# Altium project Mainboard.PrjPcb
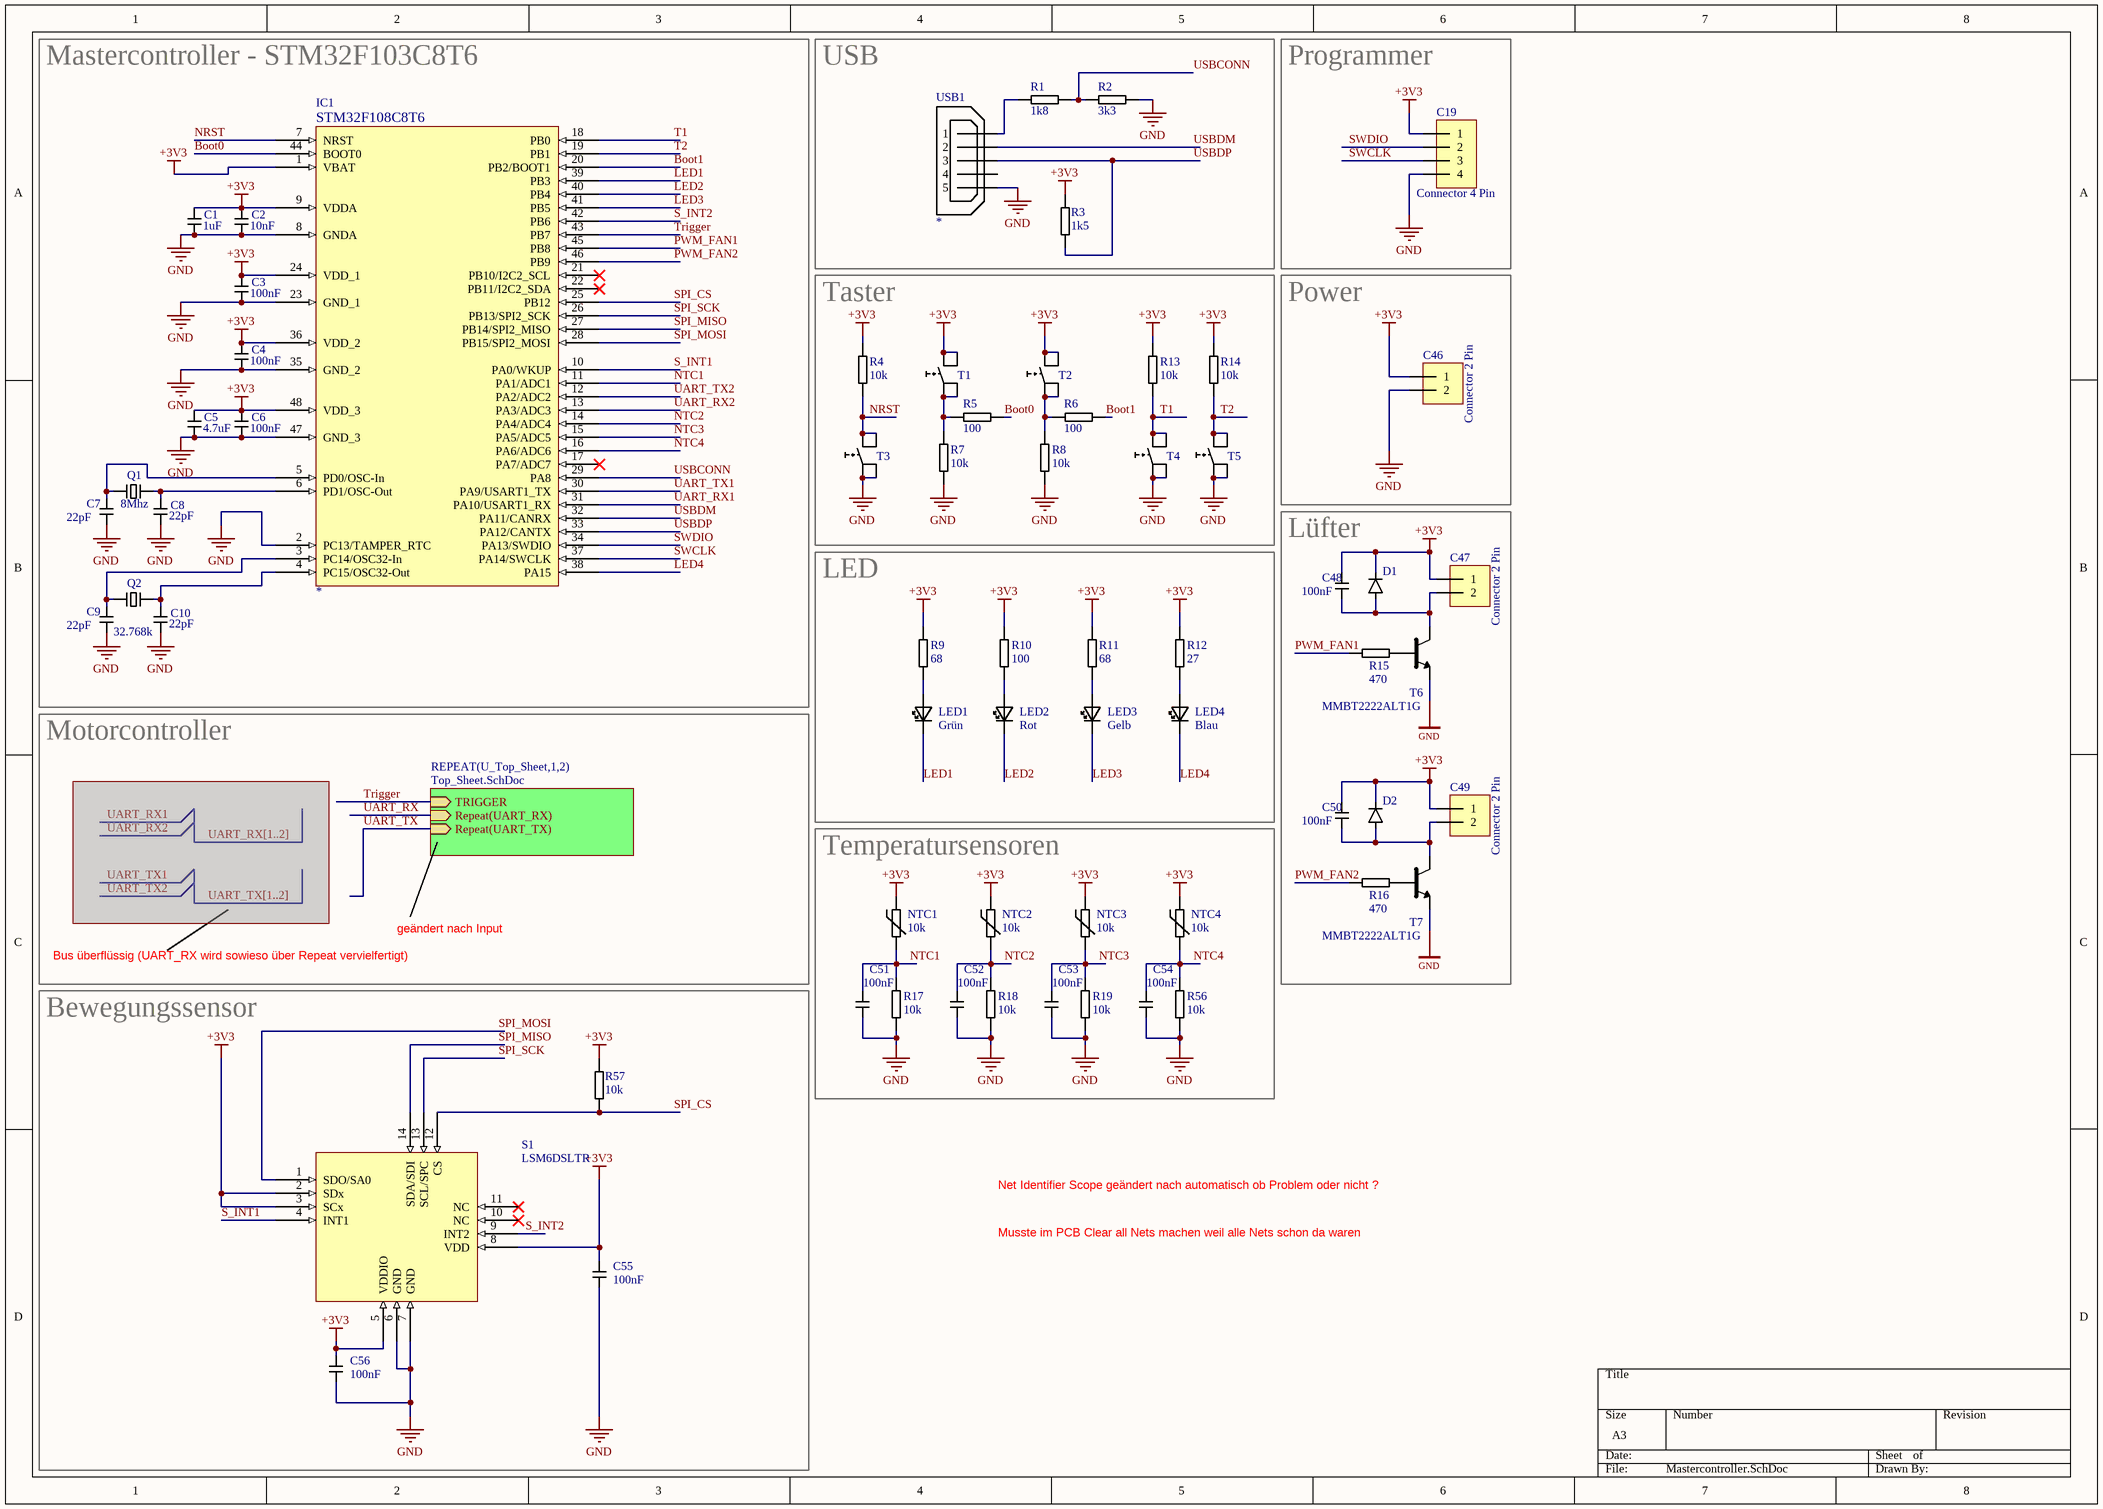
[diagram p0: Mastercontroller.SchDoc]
6 sheets, 311 parts. Net scope: hierarchical (ports join the sheet entries above them; power ports are global).
Board file: Mainboard.PcbDoc
Sheets:
  Mastercontroller.SchDoc
    U_Top_Sheet1 = Top_Sheet.SchDoc
      U_MOTOR = MOTOR.SchDoc
      U_SENSE = SENSE.SchDoc
      U_DRV8301 = DRV8301.SchDoc
      U_Motorcontroller = Motorcontroller.SchDoc
    U_Top_Sheet2 = Top_Sheet.SchDoc
      U_MOTOR = MOTOR.SchDoc
      U_SENSE = SENSE.SchDoc
      U_DRV8301 = DRV8301.SchDoc
      U_Motorcontroller = Motorcontroller.SchDoc

## Sheet Mastercontroller.SchDoc
size A3

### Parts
C1  value 1uF  [0603]  (hidden comment: *)
C2  value 10nF  [0603]  (hidden comment: *)
C3  value 100nF  [0603]  (hidden comment: *)
C4  value 100nF  [0603]  (hidden comment: *)
C5  value 4.7uF  [0603]  (hidden comment: *)
C6  value 100nF  [0603]  (hidden comment: *)
C7  value 22pF  [0603]  (hidden comment: *)
C8  value 22pF  [0603]  (hidden comment: *)
C9  value 22pF  [0603]  (hidden comment: *)
C10  value 22pF  [0603]  (hidden comment: *)
C19  Connector 4 Pin  [JST-XH 4 Pin]
C46  Connector 2 Pin  [JST-XH 2 Pin]
C47  Connector 2 Pin  [JST-XH 2 Pin]
C48  value 100nF  [0603]  (hidden comment: *)
C49  Connector 2 Pin  [JST-XH 2 Pin]
C50  value 100nF  [0603]  (hidden comment: *)
C51  value 100nF  [0603]  (hidden comment: *)
C52  value 100nF  [0603]  (hidden comment: *)
C53  value 100nF  [0603]  (hidden comment: *)
C54  value 100nF  [0603]  (hidden comment: *)
C55  value 100nF  [0603]  (hidden comment: *)
C56  value 100nF  [0603]  (hidden comment: *)
D1  Diode  [SMA]  (value not drawn)
D2  Diode  [SMA]  (value not drawn)
IC1  *  [LQFP48]
LED1  value Grün  [1206_Green]  (hidden comment: *)
LED2  value Rot  [1206_Green]  (hidden comment: *)
LED3  value Gelb  [1206_Green]  (hidden comment: *)
LED4  value Blau  [1206_Green]  (hidden comment: *)
NTC1  value 10k  [0603]  (hidden comment: NTC)
NTC2  value 10k  [0603]  (hidden comment: NTC)
NTC3  value 10k  [0603]  (hidden comment: NTC)
NTC4  value 10k  [0603]  (hidden comment: NTC)
Q1  value 8Mhz  [3225]  (hidden comment: *)
Q2  value 32.768k  [Cylinder]  (hidden comment: *)
R1  value 1k8  [0603]  (hidden comment: *)
R2  value 3k3  [0603]  (hidden comment: *)
R3  value 1k5  [0603]  (hidden comment: *)
R4  value 10k  [0603]  (hidden comment: *)
R5  value 100  [0603]  (hidden comment: *)
R6  value 100  [0603]  (hidden comment: *)
R7  value 10k  [0603]  (hidden comment: *)
R8  value 10k  [0603]  (hidden comment: *)
R9  value 68  [0603]  (hidden comment: *)
R10  value 100  [0603]  (hidden comment: *)
R11  value 68  [0603]  (hidden comment: *)
R12  value 27  [0603]  (hidden comment: *)
R13  value 10k  [0603]  (hidden comment: *)
R14  value 10k  [0603]  (hidden comment: *)
R15  value 470  [0603]  (hidden comment: *)
R16  value 470  [0603]  (hidden comment: *)
R17  value 10k  [0603]  (hidden comment: *)
R18  value 10k  [0603]  (hidden comment: *)
R19  value 10k  [0603]  (hidden comment: *)
R56  value 10k  [0603]  (hidden comment: *)
R57  value 10k  [0603]  (hidden comment: *)
S1  LSM6DSLTR  [LGA-14]
T1  Switch  [SMD_4x4]  (value not drawn)
T2  Switch  [SMD_4x4]  (value not drawn)
T3  Switch  [SMD_4x4]  (value not drawn)
T4  Switch  [SMD_4x4]  (value not drawn)
T5  Switch  [SMD_4x4]  (value not drawn)
T6  value MMBT2222ALT1G  [SOT23-BEC]  (hidden comment: *)
T7  value MMBT2222ALT1G  [SOT23-BEC]  (hidden comment: *)
USB1  *  [Micro USB]

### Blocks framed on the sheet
Mastercontroller - STM32F103C8T6: C1-C10 IC1 Q1 Q2
USB: R1-R3 USB1
Programmer: C19
Taster: R4-R8 R13 R14 T1-T5
Power: C46
LED: LED1-LED4 R9-R12
Lüfter: C47-C50 D1 D2 R15 R16 T6 T7
Temperatursensoren: C51-C54 NTC1-NTC4 R17-R19 R56
Bewegungssensor: C55 C56 R57 S1

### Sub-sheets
REPEAT(U_Top_Sheet,1,2) = Top_Sheet.SchDoc: TRIGGER (in), Repeat(UART_RX) (in), Repeat(UART_TX) (in)

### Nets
+3V3: C1.2 C2.2 C3.2 C4.2 C5.2 C6.2 C19.1 C46.1 C47.1 C48.2 C49.1 C50.2 C55.2 C56.2 D1.2 D2.2 IC1.1(VBAT) IC1.9(VDDA) IC1.24(VDD_1) IC1.36(VDD_2) IC1.48(VDD_3) NTC1.1 NTC2.1 NTC3.1 NTC4.1 R3.1 R4.2 R9.2 R10.2 R11.2 R12.2 R13.2 R14.2 R57.1 S1.2(SDx) S1.3(SCx) S1.5(VDDIO) S1.8(VDD) T1.3 T1.4 T2.3 T2.4
GND: C1.1 C2.1 C3.1 C4.1 C5.1 C6.1 C7.1 C8.1 C9.1 C10.1 C19.4 C46.2 C51.1 C52.1 C53.1 C54.1 C55.1 C56.1 IC1.2(PC13/TAMPER_RTC) IC1.8(GNDA) IC1.23(GND_1) IC1.35(GND_2) IC1.47(GND_3) R2.1 R7.1 R8.1 R17.1 R18.1 R19.1 R56.1 S1.6(GND) S1.7(GND) T3.1 T3.2 T4.1 T4.2 T5.1 T5.2 T6.E T7.E USB1.5
Boot0: IC1.44(BOOT0) R5.1
Boot1: IC1.20(PB2/BOOT1) R6.1
LED1: IC1.39(PB3) LED1.2
LED2: IC1.40(PB4) LED2.2
LED3: IC1.41(PB5) LED3.2
LED4: IC1.38(PA15) LED4.2
NRST: IC1.7(NRST) R4.1 T3.3 T3.4
NTC1: C51.2 IC1.11(PA1/ADC1) NTC1.2 R17.2
NTC2: C52.2 IC1.14(PA4/ADC4) NTC2.2 R18.2
NTC3: C53.2 IC1.15(PA5/ADC5) NTC3.2 R19.2
NTC4: C54.2 IC1.16(PA6/ADC6) NTC4.2 R56.2
PWM_FAN1: IC1.45(PB8) R15.2
PWM_FAN2: IC1.46(PB9) R16.2
S_INT1: IC1.10(PA0/WKUP) S1.4(INT1)
S_INT2: IC1.42(PB6) S1.9(INT2)
SPI_CS: IC1.25(PB12) R57.2 S1.12(CS)
SPI_MISO: IC1.27(PB14/SPI2_MISO) S1.14(SDA/SDI)
SPI_MOSI: IC1.28(PB15/SPI2_MOSI) S1.1(SDO/SA0)
SPI_SCK: IC1.26(PB13/SPI2_SCK) S1.13(SCL/SPC)
SWCLK: C19.3 IC1.37(PA14/SWCLK)
SWDIO: C19.2 IC1.34(PA13/SWDIO)
T1: IC1.18(PB0) R13.1 T4.3 T4.4
T2: IC1.19(PB1) R14.1 T5.3 T5.4
Trigger: IC1.43(PB7) ; sheet REPEAT(U_Top_Sheet,1,2)/TRIGGER
UART_RX1: IC1.31(PA10/USART1_RX)
UART_RX2: IC1.13(PA3/ADC3)
UART_TX1: IC1.30(PA9/USART1_TX)
UART_TX2: IC1.12(PA2/ADC2)
USBCONN: IC1.29(PA8) R1.1 R2.2
USBDM: IC1.32(PA11/CANRX) USB1.2
USBDP: IC1.33(PA12/CANTX) R3.2 USB1.3
NetC7_2: C7.2 IC1.5(PD0/OSC-In) Q1.3
NetC8_2: C8.2 IC1.6(PD1/OSC-Out) Q1.1
NetC9_2: C9.2 IC1.3(PC14/OSC32-In) Q2.3
NetC10_2: C10.2 IC1.4(PC15/OSC32-Out) Q2.1
NetC47_2: C47.2 C48.1 D1.1 T6.C
NetC49_2: C49.2 C50.1 D2.1 T7.C
NetLED1_1: LED1.1 R9.1
NetLED2_1: LED2.1 R10.1
NetLED3_1: LED3.1 R11.1
NetLED4_1: LED4.1 R12.1
NetR1_2: R1.2 USB1.1
NetR5_2: R5.2 R7.2 T1.1 T1.2
NetR6_2: R6.2 R8.2 T2.1 T2.2
NetR15_1: R15.1 T6.B
NetR16_1: R16.1 T7.B

Not connected (* = marked no-connect by the designer): IC1 17(PA7/ADC7)* 21(PB10/I2C2_SCL)* 22(PB11/I2C2_SDA)*; S1 10(NC)* 11(NC)*; USB1 4

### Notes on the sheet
- Motorcontroller
- Bus überflüssig (UART_RX wird sowieso über Repeat vervielfertigt)
- geändert nach Input
- Net Identifier Scope geändert nach automatisch ob Problem oder nicht ?
- Musste im PCB Clear all Nets machen weil alle Nets schon da waren

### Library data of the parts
C1-C10 C48 C50-C56 = Capacitor: Capacitor, Generic
C19 = Connector 4 Pin: 4 Pin Connector
C46 C47 C49 = Connector 2 Pin: 2 Pin Connector
IC1 = STM32F103C8T6: STM32F103C8T6 - Mainstream Performance line, ARM Cortex-M3 MCU with 64 Kbytes Flash, 72 MHz CPU, motor control, USB and CAN
LED1-LED4 = LED
NTC1-NTC4 = NTC: NTC Resistor, Generic
Q1 Q2 = Crystal: Quarz / Crystal
R1-R19 R56 R57 = Resistor: Resistor, Generic
S1 = LSM6DSLTR: LSM6DSLTR - iNEMO inertial module:   always-on 3D accelerometer and 3D gyroscope
T1-T5 = Switch: Different switches, Taster
T6 T7 = NPN Transistor: NPN Transistor zB MMBT2222ALT1G
USB1 = USB: USB Connector

## Sheet Top_Sheet.SchDoc
size A3
Used 2 times, as channels U_Top_Sheet1, U_Top_Sheet2. Parts and nets are listed once, with the designators drawn on the sheet.
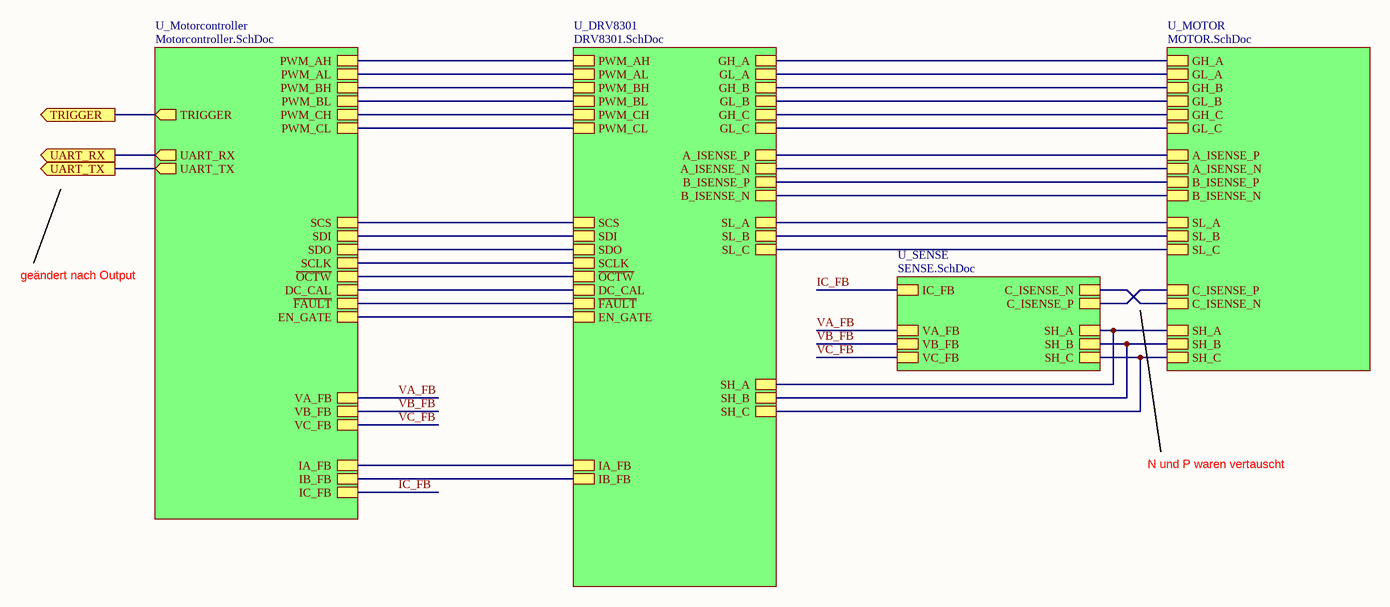
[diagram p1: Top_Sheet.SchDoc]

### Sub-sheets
U_DRV8301 = DRV8301.SchDoc: PWM_AH, PWM_AL, PWM_BH, PWM_BL, PWM_CH, PWM_CL, SDO, SDI, SCS, EN_GATE, ~{FAULT}, ~{OCTW}, GH_A, GH_B, GH_C, GL_A, GL_B, GL_C, SL_A, SL_B, SL_C, DC_CAL, SH_A, SH_B, SH_C, A_ISENSE_N, A_ISENSE_P, B_ISENSE_P, B_ISENSE_N, IA_FB, IB_FB, SCLK
U_MOTOR = MOTOR.SchDoc: GH_A, GL_A, GH_B, GL_B, GH_C, GL_C, SL_A, SL_B, SL_C, A_ISENSE_N, A_ISENSE_P, B_ISENSE_P, B_ISENSE_N, SH_C, SH_B, SH_A, C_ISENSE_P, C_ISENSE_N
U_Motorcontroller = Motorcontroller.SchDoc: IA_FB, IB_FB, IC_FB, VA_FB, VB_FB, VC_FB, PWM_AH, PWM_AL, PWM_BH, PWM_BL, PWM_CH, PWM_CL, SCS, SDO, SDI, EN_GATE, DC_CAL, SCLK, ~{OCTW}, ~{FAULT}, UART_TX (out), UART_RX (out), TRIGGER (out)
U_SENSE = SENSE.SchDoc: SH_A, VA_FB, SH_B, VB_FB, SH_C, VC_FB, IC_FB, C_ISENSE_P, C_ISENSE_N

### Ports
TRIGGER (out), UART_RX (out), UART_TX (out)

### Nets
IC_FB: sheet U_SENSE/IC_FB, sheet U_Motorcontroller/IC_FB
TRIGGER: port TRIGGER, sheet U_Motorcontroller/TRIGGER
UART_RX: port UART_RX, sheet U_Motorcontroller/UART_RX
UART_TX: port UART_TX, sheet U_Motorcontroller/UART_TX
VA_FB: sheet U_SENSE/VA_FB, sheet U_Motorcontroller/VA_FB
VB_FB: sheet U_SENSE/VB_FB, sheet U_Motorcontroller/VB_FB
VC_FB: sheet U_SENSE/VC_FB, sheet U_Motorcontroller/VC_FB
(unnamed): sheet U_MOTOR/GH_A, sheet U_DRV8301/GH_A
(unnamed): sheet U_MOTOR/GL_A, sheet U_DRV8301/GL_A  [a separate net that carries the same name]
(unnamed): sheet U_MOTOR/GH_B, sheet U_DRV8301/GH_B  [a separate net that carries the same name]
(unnamed): sheet U_MOTOR/GL_B, sheet U_DRV8301/GL_B  [a separate net that carries the same name]
(unnamed): sheet U_MOTOR/GH_C, sheet U_DRV8301/GH_C  [a separate net that carries the same name]
(unnamed): sheet U_MOTOR/GL_C, sheet U_DRV8301/GL_C  [a separate net that carries the same name]
(unnamed): sheet U_MOTOR/SL_A, sheet U_DRV8301/SL_A  [a separate net that carries the same name]
(unnamed): sheet U_MOTOR/SL_B, sheet U_DRV8301/SL_B  [a separate net that carries the same name]
(unnamed): sheet U_MOTOR/SL_C, sheet U_DRV8301/SL_C  [a separate net that carries the same name]
(unnamed): sheet U_MOTOR/A_ISENSE_N, sheet U_DRV8301/A_ISENSE_N  [a separate net that carries the same name]
(unnamed): sheet U_MOTOR/A_ISENSE_P, sheet U_DRV8301/A_ISENSE_P  [a separate net that carries the same name]
(unnamed): sheet U_MOTOR/B_ISENSE_P, sheet U_DRV8301/B_ISENSE_P  [a separate net that carries the same name]
(unnamed): sheet U_MOTOR/B_ISENSE_N, sheet U_DRV8301/B_ISENSE_N  [a separate net that carries the same name]
(unnamed): sheet U_MOTOR/SH_C, sheet U_SENSE/SH_C, sheet U_DRV8301/SH_C  [a separate net that carries the same name]
(unnamed): sheet U_MOTOR/SH_B, sheet U_SENSE/SH_B, sheet U_DRV8301/SH_B  [a separate net that carries the same name]
(unnamed): sheet U_MOTOR/SH_A, sheet U_SENSE/SH_A, sheet U_DRV8301/SH_A  [a separate net that carries the same name]
(unnamed): sheet U_MOTOR/C_ISENSE_P, sheet U_SENSE/C_ISENSE_P  [a separate net that carries the same name]
(unnamed): sheet U_MOTOR/C_ISENSE_N, sheet U_SENSE/C_ISENSE_N  [a separate net that carries the same name]
(unnamed): sheet U_DRV8301/PWM_AH, sheet U_Motorcontroller/PWM_AH  [a separate net that carries the same name]
(unnamed): sheet U_DRV8301/PWM_AL, sheet U_Motorcontroller/PWM_AL  [a separate net that carries the same name]
(unnamed): sheet U_DRV8301/PWM_BH, sheet U_Motorcontroller/PWM_BH  [a separate net that carries the same name]
(unnamed): sheet U_DRV8301/PWM_BL, sheet U_Motorcontroller/PWM_BL  [a separate net that carries the same name]
(unnamed): sheet U_DRV8301/PWM_CH, sheet U_Motorcontroller/PWM_CH  [a separate net that carries the same name]
(unnamed): sheet U_DRV8301/PWM_CL, sheet U_Motorcontroller/PWM_CL  [a separate net that carries the same name]
(unnamed): sheet U_DRV8301/SDO, sheet U_Motorcontroller/SDO  [a separate net that carries the same name]
(unnamed): sheet U_DRV8301/SDI, sheet U_Motorcontroller/SDI  [a separate net that carries the same name]
(unnamed): sheet U_DRV8301/SCS, sheet U_Motorcontroller/SCS  [a separate net that carries the same name]
(unnamed): sheet U_DRV8301/EN_GATE, sheet U_Motorcontroller/EN_GATE  [a separate net that carries the same name]
(unnamed): sheet U_DRV8301/~{FAULT}, sheet U_Motorcontroller/~{FAULT}  [a separate net that carries the same name]
(unnamed): sheet U_DRV8301/~{OCTW}, sheet U_Motorcontroller/~{OCTW}  [a separate net that carries the same name]
(unnamed): sheet U_DRV8301/DC_CAL, sheet U_Motorcontroller/DC_CAL  [a separate net that carries the same name]
(unnamed): sheet U_DRV8301/IA_FB, sheet U_Motorcontroller/IA_FB  [a separate net that carries the same name]
(unnamed): sheet U_DRV8301/IB_FB, sheet U_Motorcontroller/IB_FB  [a separate net that carries the same name]
(unnamed): sheet U_DRV8301/SCLK, sheet U_Motorcontroller/SCLK  [a separate net that carries the same name]

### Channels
U_Top_Sheet1: ports TRIGGER=Trigger UART_RX=UART_RX1 UART_TX=UART_TX1
U_Top_Sheet2: ports TRIGGER=Trigger UART_RX=UART_RX2 UART_TX=UART_TX2

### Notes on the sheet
- geändert nach Output
- N und P waren vertauscht

## Sheet MOTOR.SchDoc
size A3; Engineer: Nicholas Oborny; Revision: A.1; Name: Nicholas Oborny; Start Date: 7/23/2012
Used 2 times, as channels U_Top_Sheet1/U_MOTOR, U_Top_Sheet2/U_MOTOR. Parts and nets are listed once, with the designators drawn on the sheet.
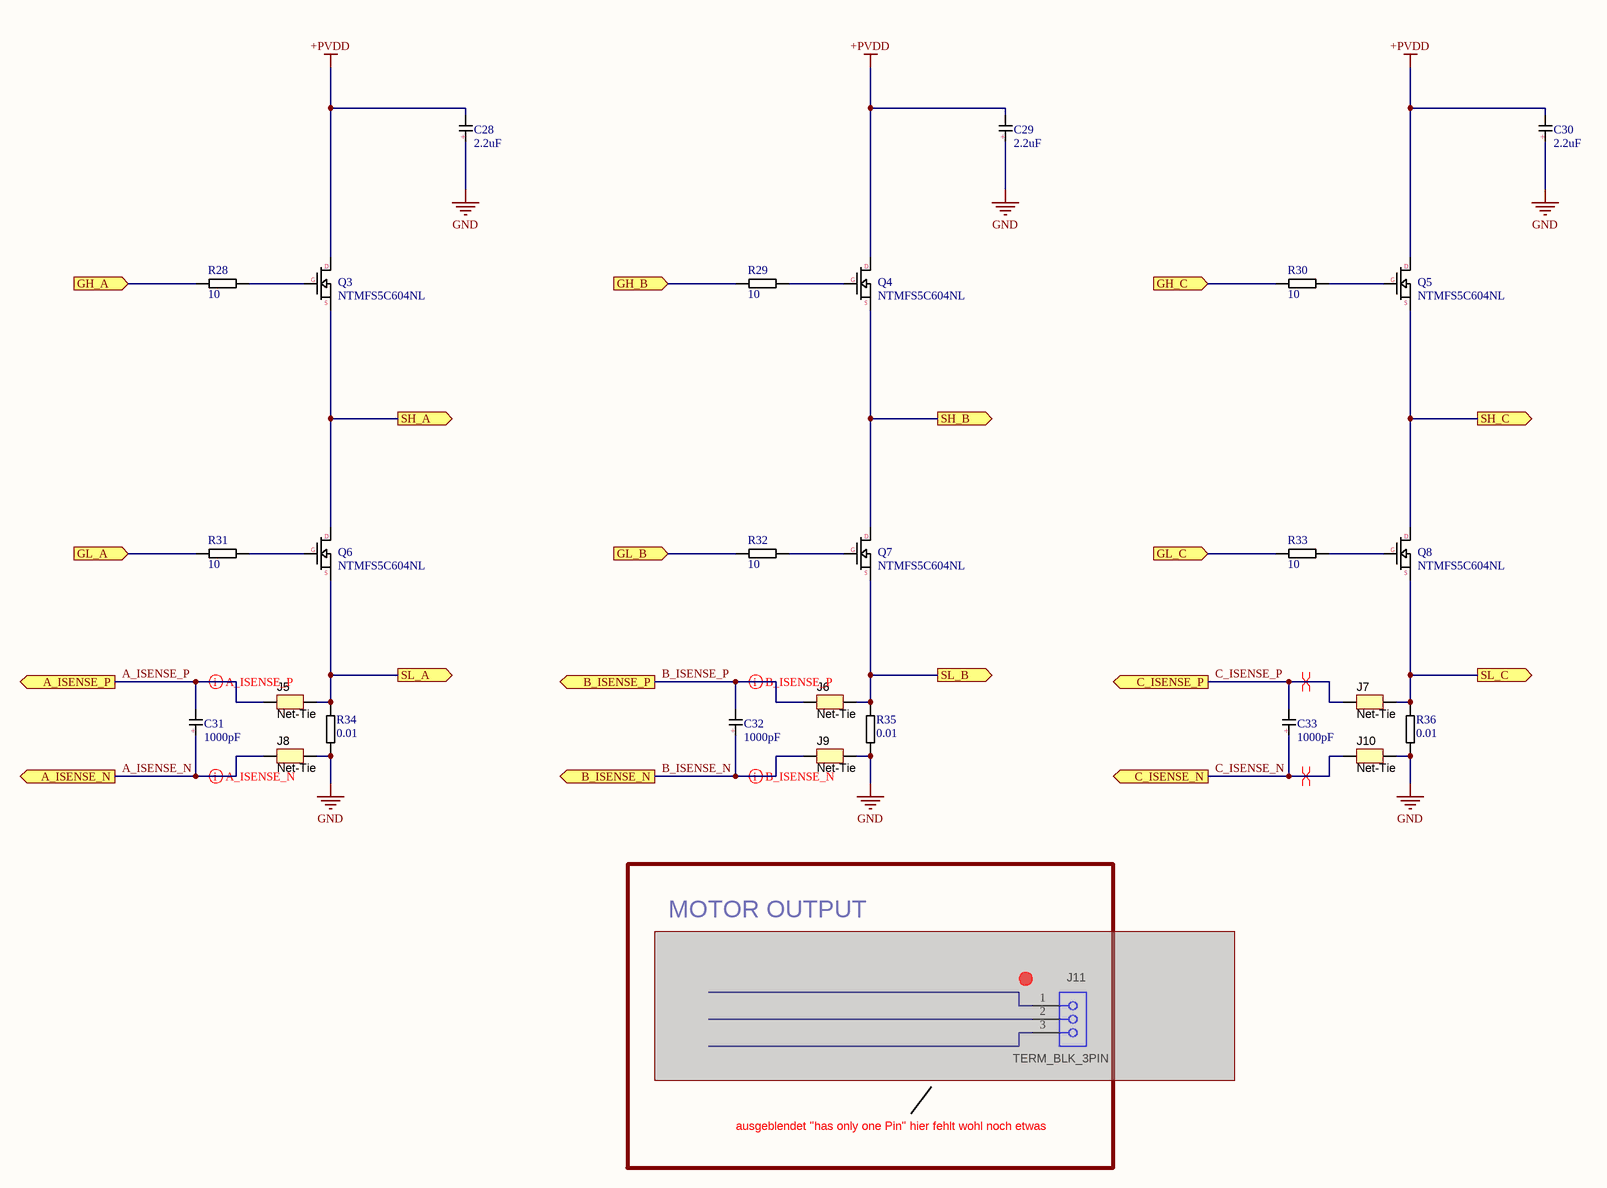
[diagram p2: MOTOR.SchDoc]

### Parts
C28  value 2.2uF  [0603]  (hidden comment: Capacitor)
C29  value 2.2uF  [0603]  (hidden comment: Capacitor)
C30  value 2.2uF  [0603]  (hidden comment: Capacitor)
C31  value 1000pF  [0603]  (hidden comment: Capacitor)
C32  value 1000pF  [0603]  (hidden comment: Capacitor)
C33  value 1000pF  [0603]  (hidden comment: Capacitor)
J5  Net-Tie  [Net-Tie_10mil]  (net tie, no BOM)
J6  Net-Tie  [Net-Tie_10mil]  (net tie, no BOM)
J7  Net-Tie  [Net-Tie_10mil]  (net tie, no BOM)
J8  Net-Tie  [Net-Tie_10mil]  (net tie, no BOM)
J9  Net-Tie  [Net-Tie_10mil]  (net tie, no BOM)
J10  Net-Tie  [Net-Tie_10mil]  (net tie, no BOM)
J11  TERM_BLK_3PIN  [CONN_ED120_3DS]  (masked out: inside a compile mask, not in the netlist)
Q3  NTMFS5C604NL  [DFN-5]
Q4  NTMFS5C604NL  [DFN-5]
Q5  NTMFS5C604NL  [DFN-5]
Q6  NTMFS5C604NL  [DFN-5]
Q7  NTMFS5C604NL  [DFN-5]
Q8  NTMFS5C604NL  [DFN-5]
R28  value 10  [0603]  (hidden comment: Resistor)
R29  value 10  [0603]  (hidden comment: Resistor)
R30  value 10  [0603]  (hidden comment: Resistor)
R31  value 10  [0603]  (hidden comment: Resistor)
R32  value 10  [0603]  (hidden comment: Resistor)
R33  value 10  [0603]  (hidden comment: Resistor)
R34  value 0.01  [2512]  (hidden comment: Resistor)
R35  value 0.01  [2512]  (hidden comment: Resistor)
R36  value 0.01  [2512]  (hidden comment: Resistor)

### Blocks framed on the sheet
MOTOR OUTPUT: J11

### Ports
A_ISENSE_N, A_ISENSE_P, B_ISENSE_N, B_ISENSE_P, C_ISENSE_N, C_ISENSE_P, GH_A, GH_B, GH_C, GL_A, GL_B, GL_C, SH_A, SH_B, SH_C, SL_A, SL_B, SL_C

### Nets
+PVDD: C28.2 C29.2 C30.2 Q3.3(D) Q4.3(D) Q5.3(D)
GND: C28.1 C29.1 C30.1 J8.1 J9.1 J10.1 R34.1 R35.1 R36.1
A_ISENSE_N: C31.1 J8.2 ; port A_ISENSE_N
A_ISENSE_P: C31.2 J5.2 ; port A_ISENSE_P
B_ISENSE_N: C32.1 J9.2 ; port B_ISENSE_N
B_ISENSE_P: C32.2 J6.2 ; port B_ISENSE_P
C_ISENSE_N: C33.1 J10.2 ; port C_ISENSE_N
C_ISENSE_P: C33.2 J7.2 ; port C_ISENSE_P
GH_A: R28.2 ; port GH_A
GH_B: R29.2 ; port GH_B
GH_C: R30.2 ; port GH_C
GL_A: R31.2 ; port GL_A
GL_B: R32.2 ; port GL_B
GL_C: R33.2 ; port GL_C
SH_A: Q3.1(S) Q6.3(D) ; port SH_A
SH_B: Q4.1(S) Q7.3(D) ; port SH_B
SH_C: Q5.1(S) Q8.3(D) ; port SH_C
SL_A: J5.1 Q6.1(S) R34.2 ; port SL_A
SL_B: J6.1 Q7.1(S) R35.2 ; port SL_B
SL_C: J7.1 Q8.1(S) R36.2 ; port SL_C
NetQ3_2: Q3.2(G) R28.1
NetQ4_2: Q4.2(G) R29.1
NetQ5_2: Q5.2(G) R30.1
NetQ6_2: Q6.2(G) R31.1
NetQ7_2: Q7.2(G) R32.1
NetQ8_2: Q8.2(G) R33.1

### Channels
U_Top_Sheet1/U_MOTOR: designators end in _U_Top_Sheet1_U_MOTOR; ports A_ISENSE_N=A_ISENSE_N A_ISENSE_P=A_ISENSE_P B_ISENSE_N=B_ISENSE_N B_ISENSE_P=B_ISENSE_P C_ISENSE_N=C_ISENSE_N C_ISENSE_P=C_ISENSE_P GH_A=GH_A GH_B=GH_B GH_C=GH_C GL_A=GL_A GL_B=GL_B GL_C=GL_C SH_A=SH_A SH_B=SH_B SH_C=SH_C SL_A=SL_A SL_B=SL_B SL_C=SL_C
U_Top_Sheet2/U_MOTOR: designators end in _U_Top_Sheet2_U_MOTOR; ports A_ISENSE_N=A_ISENSE_N A_ISENSE_P=A_ISENSE_P B_ISENSE_N=B_ISENSE_N B_ISENSE_P=B_ISENSE_P C_ISENSE_N=C_ISENSE_N C_ISENSE_P=C_ISENSE_P GH_A=GH_A GH_B=GH_B GH_C=GH_C GL_A=GL_A GL_B=GL_B GL_C=GL_C SH_A=SH_A SH_B=SH_B SH_C=SH_C SL_A=SL_A SL_B=SL_B SL_C=SL_C

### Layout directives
differential pair: A_ISENSE_N, A_ISENSE_P, B_ISENSE_N, B_ISENSE_P, C_ISENSE_N, C_ISENSE_P

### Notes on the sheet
- ausgeblendet "has only one Pin" hier fehlt wohl noch etwas

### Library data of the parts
C28-C33 = Capacitor: Capacitor, Generic, 100V
J5-J10 = Net-Tie: Single point connection between nets.; SymbolCreator: codlsc
J11 = ED120/3DS: TERMINAL BLOCK 5.08MM VERT 3POS; PartNumber: OSTTA034163; Manufacturer: On-Shore Technology; SymbolCreator: a0412235; U/M: EA; Value: 3 Pin Header
Q3-Q8 = NTMFS5C604NL: MOSFET NTMFS5C604NL - Power MOSFET  60 V, 1.2m, 287 A, Single N−Channel
R28-R36 = Resistor: Resistor, Generic

## Sheet SENSE.SchDoc
size A3; Engineer: Nicholas Oborny; Revision: A.1; Name: Nicholas Oborny; Start Date: 7/23/2012
Used 2 times, as channels U_Top_Sheet1/U_SENSE, U_Top_Sheet2/U_SENSE. Parts and nets are listed once, with the designators drawn on the sheet.
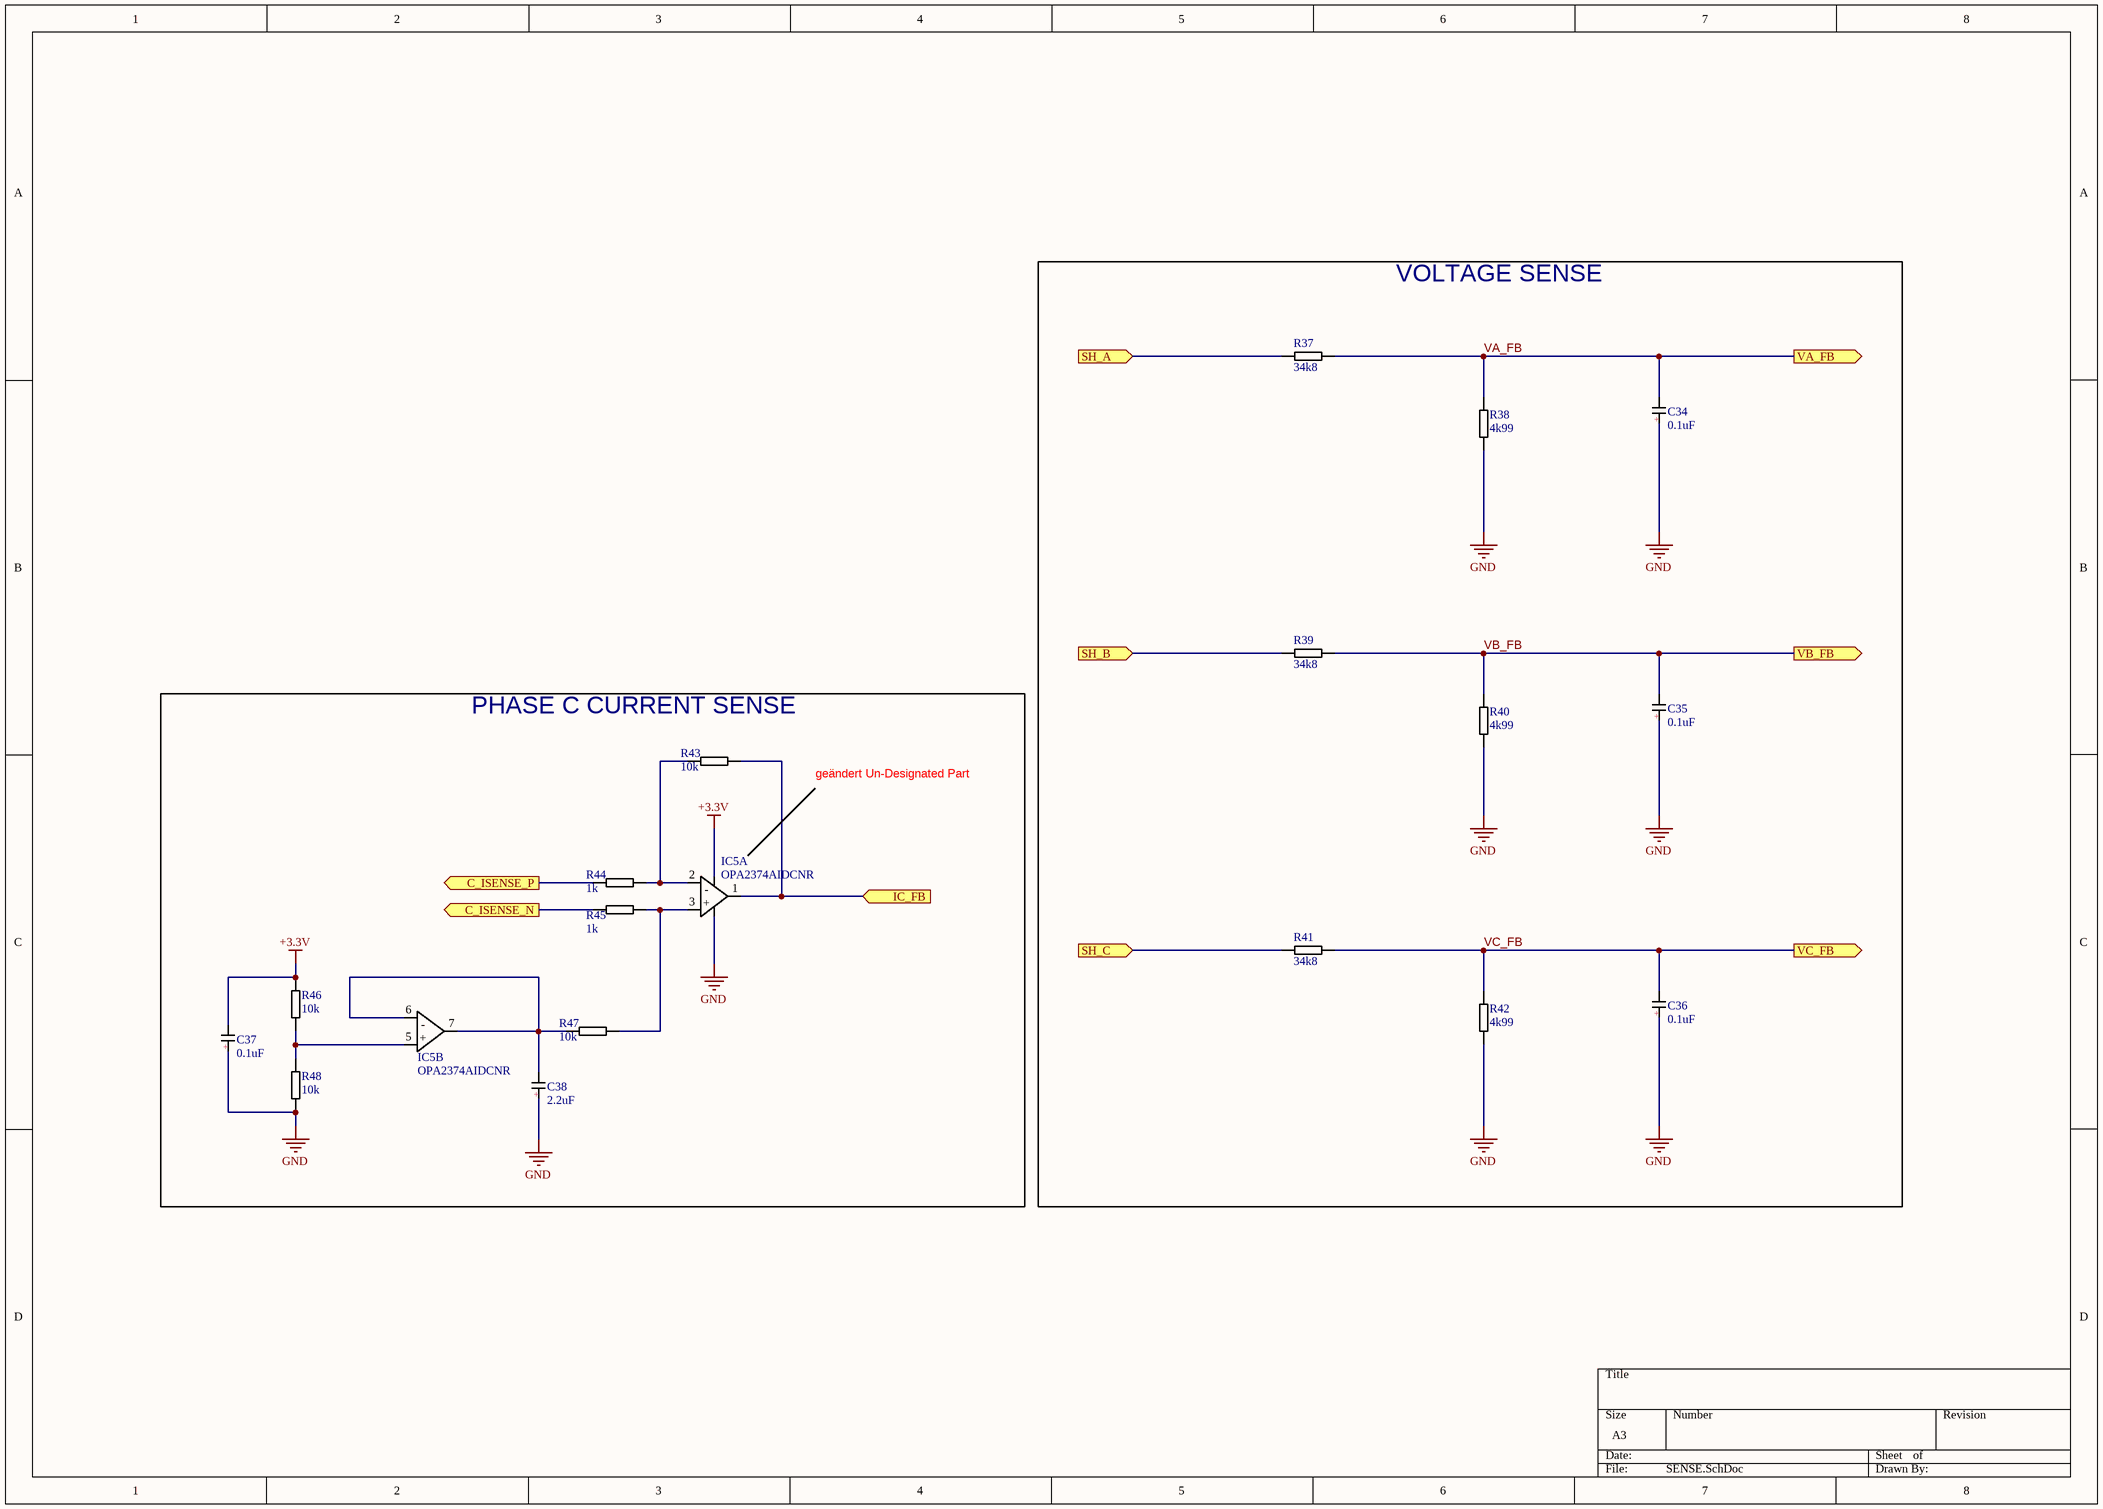
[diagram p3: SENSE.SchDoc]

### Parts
C34  value 0.1uF  [0603]  (hidden comment: Capacitor)
C35  value 0.1uF  [0603]  (hidden comment: Capacitor)
C36  value 0.1uF  [0603]  (hidden comment: Capacitor)
C37  value 0.1uF  [0603]  (hidden comment: Capacitor)
C38  value 2.2uF  [0603]  (hidden comment: Capacitor)
IC5  OPA2374AIDCNR  [SOT23-8]  (parts A,B of 2)
R37  value 34k8  [0603]  (hidden comment: Resistor)
R38  value 4k99  [0603]  (hidden comment: Resistor)
R39  value 34k8  [0603]  (hidden comment: Resistor)
R40  value 4k99  [0603]  (hidden comment: Resistor)
R41  value 34k8  [0603]  (hidden comment: Resistor)
R42  value 4k99  [0603]  (hidden comment: Resistor)
R43  value 10k  [0603]  (hidden comment: Resistor)
R44  value 1k  [0603]  (hidden comment: Resistor)
R45  value 1k  [0603]  (hidden comment: Resistor)
R46  value 10k  [0603]  (hidden comment: Resistor)
R47  value 10k  [0603]  (hidden comment: Resistor)
R48  value 10k  [0603]  (hidden comment: Resistor)

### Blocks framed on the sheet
VOLTAGE SENSE: C34-C36 R37-R42
PHASE C CURRENT SENSE: C37 C38 IC5 R43-R48

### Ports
C_ISENSE_N, C_ISENSE_P, IC_FB, SH_A, SH_B, SH_C, VA_FB, VB_FB, VC_FB

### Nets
+3.3V: C37.2 IC5.8(VCC) R46.2
GND: C34.1 C35.1 C36.1 C37.1 C38.1 IC5.4(GND) R38.1 R40.1 R42.1 R48.1
C_ISENSE_N: R45.1 ; port C_ISENSE_N
C_ISENSE_P: R44.1 ; port C_ISENSE_P
IC_FB: IC5.1(A) R43.2 ; port IC_FB
SH_A: R37.2 ; port SH_A
SH_B: R39.2 ; port SH_B
SH_C: R41.2 ; port SH_C
VA_FB: C34.2 R37.1 R38.2 ; port VA_FB
VB_FB: C35.2 R39.1 R40.2 ; port VB_FB
VC_FB: C36.2 R41.1 R42.2 ; port VC_FB
NetC38_2: C38.2 IC5.6(-B) IC5.7(B) R47.1
NetIC5_2: IC5.2(-A) R43.1 R44.2
NetIC5_3: IC5.3(+A) R45.2 R47.2
NetIC5_5: IC5.5(+B) R46.1 R48.2

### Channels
U_Top_Sheet1/U_SENSE: designators end in _U_Top_Sheet1_U_SENSE; ports C_ISENSE_N=C_ISENSE_N C_ISENSE_P=C_ISENSE_P IC_FB=IC_FB_U_Top_Sheet1 SH_A=SH_A SH_B=SH_B SH_C=SH_C VA_FB=VA_FB_U_Top_Sheet1 VB_FB=VB_FB_U_Top_Sheet1 VC_FB=VC_FB_U_Top_Sheet1
U_Top_Sheet2/U_SENSE: designators end in _U_Top_Sheet2_U_SENSE; ports C_ISENSE_N=C_ISENSE_N C_ISENSE_P=C_ISENSE_P IC_FB=IC_FB_U_Top_Sheet2 SH_A=SH_A SH_B=SH_B SH_C=SH_C VA_FB=VA_FB_U_Top_Sheet2 VB_FB=VB_FB_U_Top_Sheet2 VC_FB=VC_FB_U_Top_Sheet2

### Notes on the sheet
- geändert Un-Designated Part

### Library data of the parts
C34-C38 = Capacitor: Capacitor, Generic, 100V
IC5 = OPA2374AIDCNR: OPA2374AIDCNR - OPAx373, OPAx374 6.5-MHz, 585-µA, Rail-to-Rail I/O  CMOS Operational Amplifier
R37-R48 = Resistor: Resistor, Generic

## Sheet DRV8301.SchDoc
size A3; Engineer: Nicholas Oborny; Revision: A.1; Name: Nicholas Oborny; Start Date: 7/23/2012
Used 2 times, as channels U_Top_Sheet1/U_DRV8301, U_Top_Sheet2/U_DRV8301. Parts and nets are listed once, with the designators drawn on the sheet.
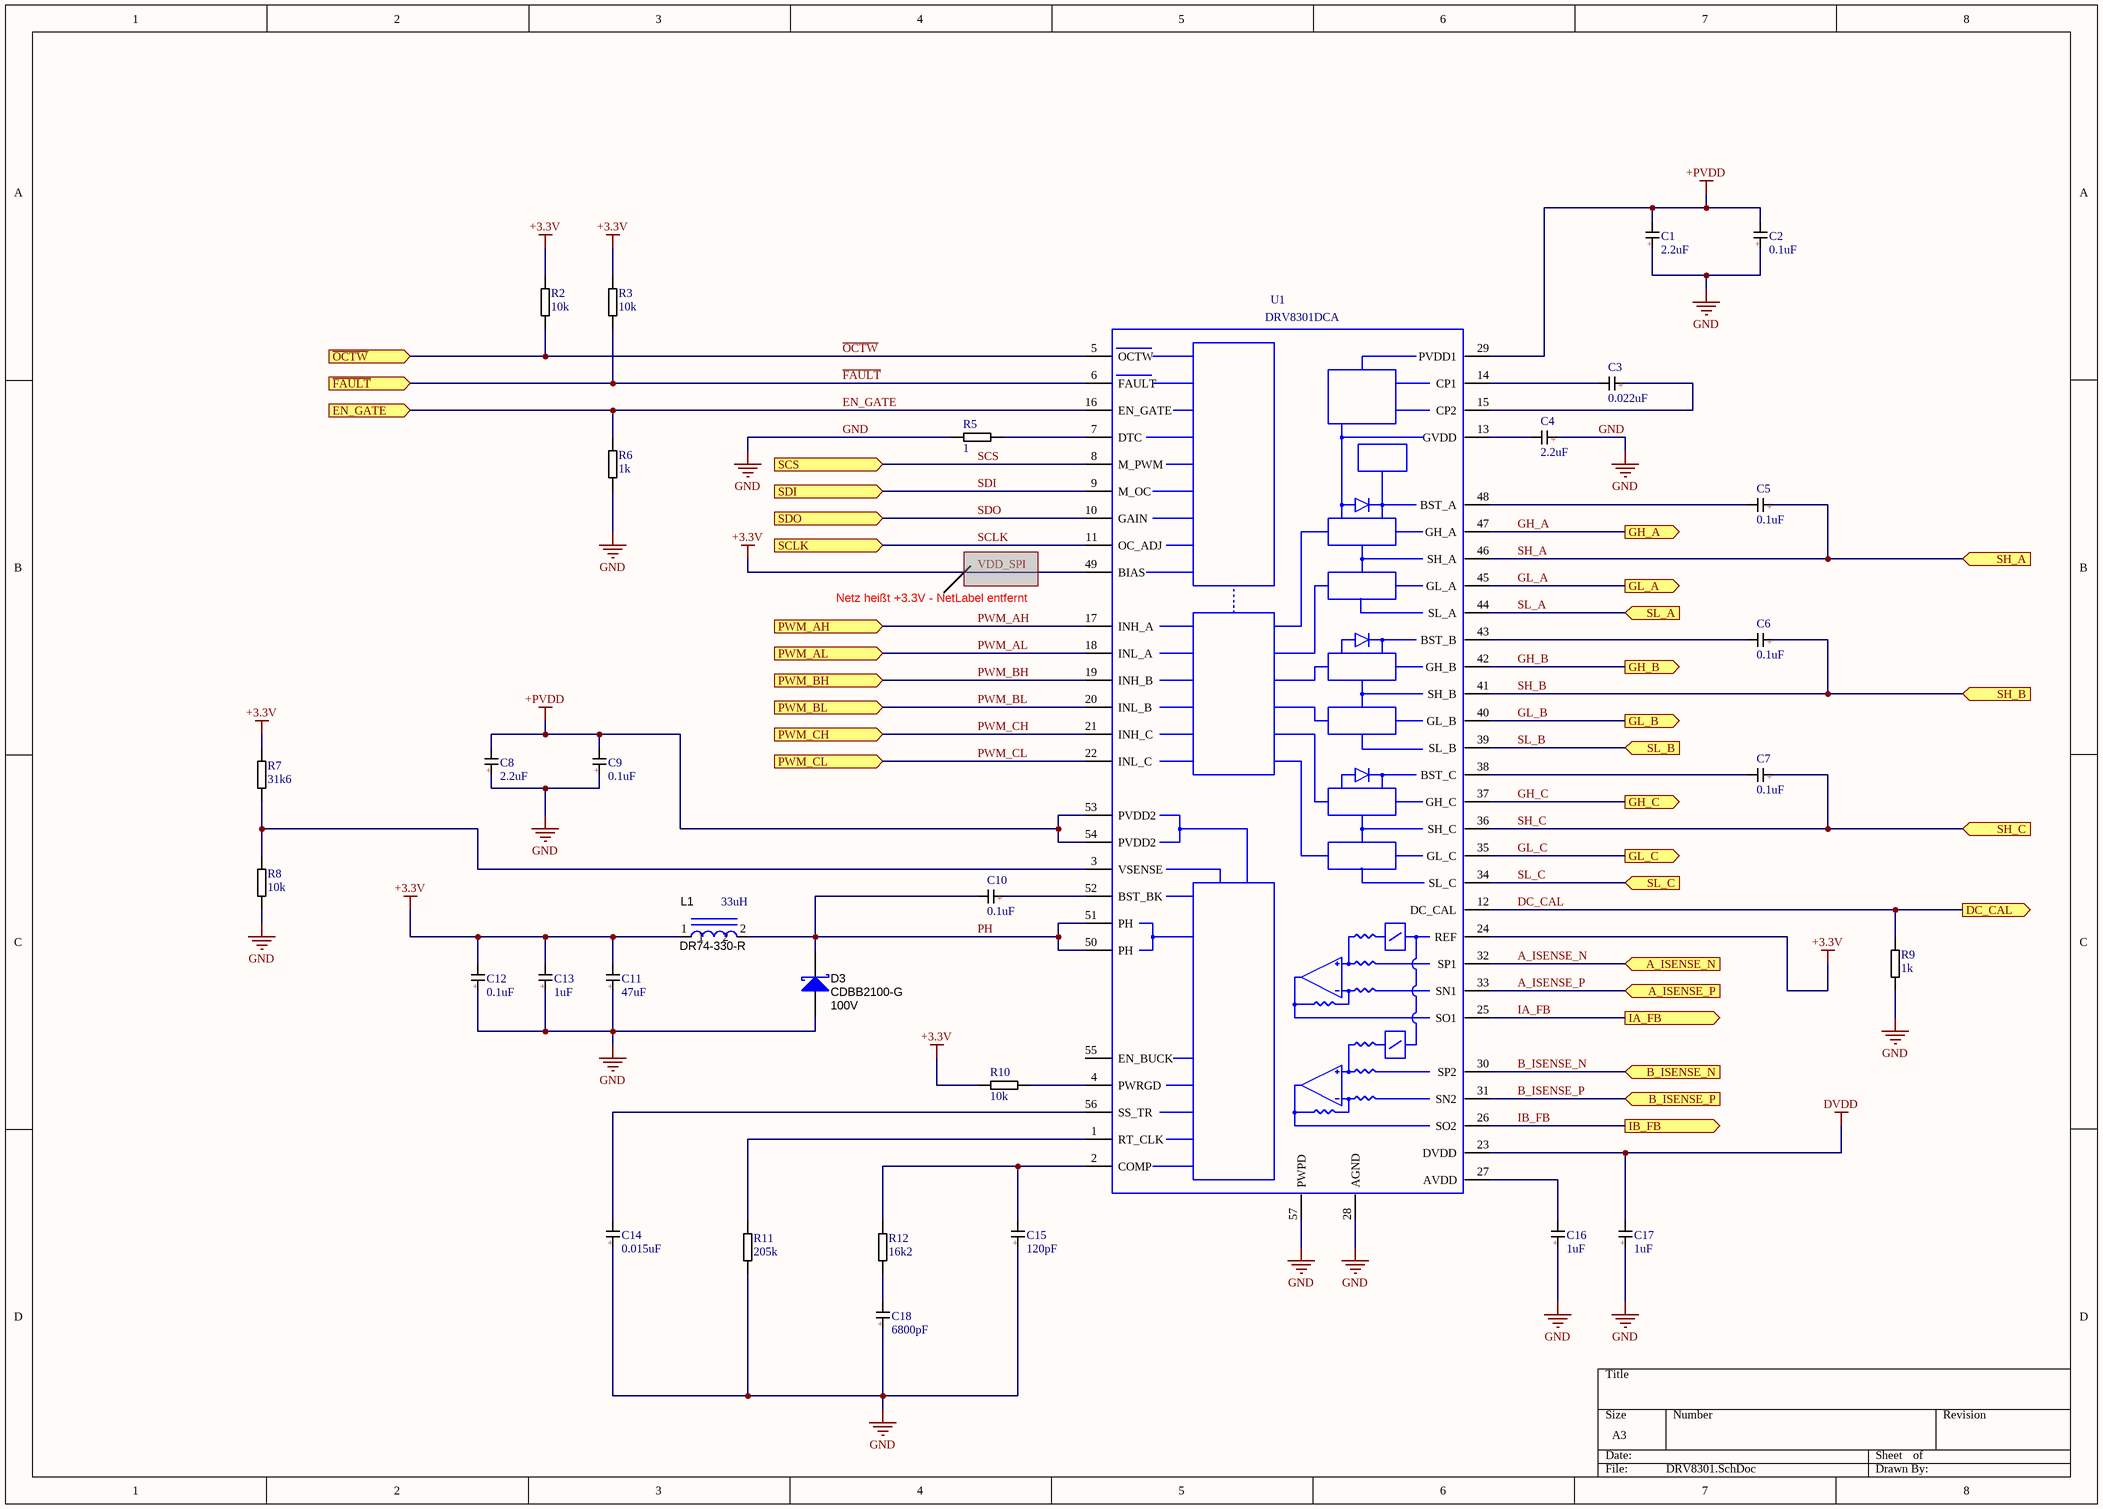
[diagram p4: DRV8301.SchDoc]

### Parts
C1  value 2.2uF  [0603]  (hidden comment: Capacitor)
C2  value 0.1uF  [0603]  (hidden comment: Capacitor)
C3  value 0.022uF  [0603]  (hidden comment: Capacitor)
C4  value 2.2uF  [0603]  (hidden comment: Capacitor)
C5  value 0.1uF  [0603]  (hidden comment: Capacitor)
C6  value 0.1uF  [0603]  (hidden comment: Capacitor)
C7  value 0.1uF  [0603]  (hidden comment: Capacitor)
C8  value 2.2uF  [0603]  (hidden comment: Capacitor)
C9  value 0.1uF  [0603]  (hidden comment: Capacitor)
C10  value 0.1uF  [0603]  (hidden comment: Capacitor)
C11  value 47uF  [0603]  (hidden comment: Capacitor)
C12  value 0.1uF  [0603]  (hidden comment: Capacitor)
C13  value 1uF  [0603]  (hidden comment: Capacitor)
C14  value 0.015uF  [0603]  (hidden comment: Capacitor)
C15  value 120pF  [0603]  (hidden comment: Capacitor)
C16  value 1uF  [0603]  (hidden comment: Capacitor)
C17  value 1uF  [0603]  (hidden comment: Capacitor)
C18  value 6800pF  [0603]  (hidden comment: Capacitor)
D3  CDBB2100-G  value 100V  [SMB]
L1  DR74-330-R  value 33uH  [IND_DR74]
R2  value 10k  [0603]  (hidden comment: Resistor)
R3  value 10k  [0603]  (hidden comment: Resistor)
R5  value 1  [0603]  (hidden comment: Resistor)
R6  value 1k  [0603]  (hidden comment: Resistor)
R7  value 31k6  [0603]  (hidden comment: Resistor)
R8  value 10k  [0603]  (hidden comment: Resistor)
R9  value 1k  [0603]  (hidden comment: Resistor)
R10  value 10k  [0603]  (hidden comment: Resistor)
R11  value 205k  [0603]  (hidden comment: Resistor)
R12  value 16k2  [0603]  (hidden comment: Resistor)
U1  DRV8301DCA  [DCA_56P]

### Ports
A_ISENSE_N, A_ISENSE_P, B_ISENSE_N, B_ISENSE_P, DC_CAL, EN_GATE, GH_A, GH_B, GH_C, GL_A, GL_B, GL_C, IA_FB, IB_FB, PWM_AH, PWM_AL, PWM_BH, PWM_BL, PWM_CH, PWM_CL, SCLK, SCS, SDI, SDO, SH_A, SH_B, SH_C, SL_A, SL_B, SL_C, ~{FAULT}, ~{OCTW}

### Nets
+3.3V: C11.2 C12.2 C13.2 L1.1 R2.1 R3.1 R7.1 R10.2 U1.24(REF) U1.49(BIAS)
+PVDD: C1.2 C2.2 C8.2 C9.2 U1.29(PVDD1) U1.53(PVDD2) U1.54(PVDD2)
DVDD: C17.2 U1.23(DVDD)
GND: C1.1 C2.1 C4.1 C8.1 C9.1 C11.1 C12.1 C13.1 C14.1 C15.1 C16.1 C17.1 C18.1 D3.2(A) R5.2 R6.2 R8.2 R9.2 R11.2 U1.28(AGND) U1.57(PWPD)
~{FAULT}: R3.2 U1.6(FAULT) ; port ~{FAULT}
~{OCTW}: R2.2 U1.5(OCTW) ; port ~{OCTW}
A_ISENSE_N: U1.32(SP1) ; port A_ISENSE_N
A_ISENSE_P: U1.33(SN1) ; port A_ISENSE_P
B_ISENSE_N: U1.30(SP2) ; port B_ISENSE_N
B_ISENSE_P: U1.31(SN2) ; port B_ISENSE_P
DC_CAL: R9.1 U1.12(DC_CAL) ; port DC_CAL
EN_GATE: R6.1 U1.16(EN_GATE) ; port EN_GATE
GH_A: U1.47(GH_A) ; port GH_A
GH_B: U1.42(GH_B) ; port GH_B
GH_C: U1.37(GH_C) ; port GH_C
GL_A: U1.45(GL_A) ; port GL_A
GL_B: U1.40(GL_B) ; port GL_B
GL_C: U1.35(GL_C) ; port GL_C
IA_FB: U1.25(SO1) ; port IA_FB
IB_FB: U1.26(SO2) ; port IB_FB
PH: C10.2 D3.1(K) L1.2 U1.50(PH) U1.51(PH)
PWM_AH: U1.17(INH_A) ; port PWM_AH
PWM_AL: U1.18(INL_A) ; port PWM_AL
PWM_BH: U1.19(INH_B) ; port PWM_BH
PWM_BL: U1.20(INL_B) ; port PWM_BL
PWM_CH: U1.21(INH_C) ; port PWM_CH
PWM_CL: U1.22(INL_C) ; port PWM_CL
SCLK: U1.11(OC_ADJ) ; port SCLK
SCS: U1.8(M_PWM) ; port SCS
SDI: U1.9(M_OC) ; port SDI
SDO: U1.10(GAIN) ; port SDO
SH_A: C5.1 U1.46(SH_A) ; port SH_A
SH_B: C6.1 U1.41(SH_B) ; port SH_B
SH_C: C7.1 U1.36(SH_C) ; port SH_C
SL_A: U1.44(SL_A) ; port SL_A
SL_B: U1.39(SL_B) ; port SL_B
SL_C: U1.34(SL_C) ; port SL_C
NetC3_1: C3.1 U1.15(CP2)
NetC3_2: C3.2 U1.14(CP1)
NetC4_2: C4.2 U1.13(GVDD)
NetC5_2: C5.2 U1.48(BST_A)
NetC6_2: C6.2 U1.43(BST_B)
NetC7_2: C7.2 U1.38(BST_C)
NetC10_1: C10.1 U1.52(BST_BK)
NetC14_2: C14.2 U1.56(SS_TR)
NetC15_2: C15.2 R12.1 U1.2(COMP)
NetC16_2: C16.2 U1.27(AVDD)
NetC18_2: C18.2 R12.2
NetR5_1: R5.1 U1.7(DTC)
NetR7_2: R7.2 R8.1 U1.3(VSENSE)
NetR10_1: R10.1 U1.4(PWRGD)
NetR11_1: R11.1 U1.1(RT_CLK)

Not connected (* = marked no-connect by the designer): U1 55(EN_BUCK)

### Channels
U_Top_Sheet1/U_DRV8301: designators C1=C1_U_Top_Sheet1_U_DRV8301 C2=C2_U_Top_Sheet1_U_DRV8301 C3=C3_U_Top_Sheet1_U_DRV8301 C4=C4_U_Top_Sheet1_U_DRV8301 C5=C5_U_Top_Sheet1_U_DRV8301 C6=C6_U_Top_Sheet1_U_DRV8301 C7=C7_U_Top_Sheet1_U_DRV8301 C8=C8_U_Top_Sheet1_U_DRV8301 C9=C9_U_Top_Sheet1_U_DRV8301 C10=C10_U_Top_Sheet1_U_DRV8301 C11=C11_U_Top_Sheet1_U_DRV8301 C12=C12_U_Top_Sheet1_U_DRV8301 C13=C13_U_Top_Sheet1_U_DRV8301 C14=C14_U_Top_Sheet1_U_DRV8301 C15=C15_U_Top_Sheet1_U_DRV8301 C16=C16_U_Top_Sheet1_U_DRV8301 C17=C17_U_Top_Sheet1_U_DRV8301 C18=C18_U_Top_Sheet1_U_DRV8301 D3=D3_U_DRV83011 L1=L1_U_Top_Sheet1_U_DRV8301 R2=R2_U_Top_Sheet1_U_DRV8301 R3=R3_U_Top_Sheet1_U_DRV8301 R5=R5_U_Top_Sheet1_U_DRV8301 R6=R6_U_Top_Sheet1_U_DRV8301 R7=R7_U_Top_Sheet1_U_DRV8301 R8=R8_U_Top_Sheet1_U_DRV8301 R9=R9_U_Top_Sheet1_U_DRV8301 R10=R10_U_Top_Sheet1_U_DRV8301 R11=R11_U_Top_Sheet1_U_DRV8301 R12=R12_U_Top_Sheet1_U_DRV8301 U1=U1_U_Top_Sheet1_U_DRV8301; ports A_ISENSE_N=A_ISENSE_N A_ISENSE_P=A_ISENSE_P B_ISENSE_N=B_ISENSE_N B_ISENSE_P=B_ISENSE_P DC_CAL=DC_CAL EN_GATE=EN_GATE GH_A=GH_A GH_B=GH_B GH_C=GH_C GL_A=GL_A GL_B=GL_B GL_C=GL_C IA_FB=IA_FB IB_FB=IB_FB PWM_AH=GPIO0 PWM_AL=GPIO1 PWM_BH=GPIO2 PWM_BL=GPIO3 PWM_CH=GPIO4 PWM_CL=GPIO5 SCLK=GPIO18 SCS=GPIO19 SDI=GPIO16 SDO=GPIO17 SH_A=SH_A SH_B=SH_B SH_C=SH_C SL_A=SL_A SL_B=SL_B SL_C=SL_C ~{FAULT}=~{FAULT} ~{OCTW}=~{OCTW}
U_Top_Sheet2/U_DRV8301: designators C1=C1_U_Top_Sheet2_U_DRV8301 C2=C2_U_Top_Sheet2_U_DRV8301 C3=C3_U_Top_Sheet2_U_DRV8301 C4=C4_U_Top_Sheet2_U_DRV8301 C5=C5_U_Top_Sheet2_U_DRV8301 C6=C6_U_Top_Sheet2_U_DRV8301 C7=C7_U_Top_Sheet2_U_DRV8301 C8=C8_U_Top_Sheet2_U_DRV8301 C9=C9_U_Top_Sheet2_U_DRV8301 C10=C10_U_Top_Sheet2_U_DRV8301 C11=C11_U_Top_Sheet2_U_DRV8301 C12=C12_U_Top_Sheet2_U_DRV8301 C13=C13_U_Top_Sheet2_U_DRV8301 C14=C14_U_Top_Sheet2_U_DRV8301 C15=C15_U_Top_Sheet2_U_DRV8301 C16=C16_U_Top_Sheet2_U_DRV8301 C17=C17_U_Top_Sheet2_U_DRV8301 C18=C18_U_Top_Sheet2_U_DRV8301 D3=D3_U_DRV83012 L1=L1_U_Top_Sheet2_U_DRV8301 R2=R2_U_Top_Sheet2_U_DRV8301 R3=R3_U_Top_Sheet2_U_DRV8301 R5=R5_U_Top_Sheet2_U_DRV8301 R6=R6_U_Top_Sheet2_U_DRV8301 R7=R7_U_Top_Sheet2_U_DRV8301 R8=R8_U_Top_Sheet2_U_DRV8301 R9=R9_U_Top_Sheet2_U_DRV8301 R10=R10_U_Top_Sheet2_U_DRV8301 R11=R11_U_Top_Sheet2_U_DRV8301 R12=R12_U_Top_Sheet2_U_DRV8301 U1=U1_U_Top_Sheet2_U_DRV8301; ports A_ISENSE_N=A_ISENSE_N A_ISENSE_P=A_ISENSE_P B_ISENSE_N=B_ISENSE_N B_ISENSE_P=B_ISENSE_P DC_CAL=DC_CAL EN_GATE=EN_GATE GH_A=GH_A GH_B=GH_B GH_C=GH_C GL_A=GL_A GL_B=GL_B GL_C=GL_C IA_FB=IA_FB IB_FB=IB_FB PWM_AH=GPIO0 PWM_AL=GPIO1 PWM_BH=GPIO2 PWM_BL=GPIO3 PWM_CH=GPIO4 PWM_CL=GPIO5 SCLK=GPIO18 SCS=GPIO19 SDI=GPIO16 SDO=GPIO17 SH_A=SH_A SH_B=SH_B SH_C=SH_C SL_A=SL_A SL_B=SL_B SL_C=SL_C ~{FAULT}=~{FAULT} ~{OCTW}=~{OCTW}

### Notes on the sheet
- Netz heißt +3.3V - NetLabel entfernt

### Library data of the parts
C1-C11 C13-C18 = Capacitor: Capacitor, Generic, 100V
C12 = Capacitor: Capacitor, Generic
D3 = CDBC5100-G: Diode, Schottky, 100V, 2A, SMB; Manufacturer: Comchip Technology; U/M: EA; Vf_V: 0.85; Value2: 0.85V; Io_A: 2; Vr_V: 100; TJmax_C: 125
L1 = IND_DR74-XXX: INDUCTOR SHIELD PWR 33UH SMD; Manufacturer: Cooper Bussmann; Area: 122500
R2 R3 R5-R12 = Resistor: Resistor, Generic
U1 = DRV8302DCA_ERIC: IC, 3 Phase Pre-Driver with Dual Current Shunt Amplifiers and Buck Regulator-Hardware Controlled; Manufacturer: Texas Instruments; Area: 154.44 mm; Vendor: Supplied

## Sheet Motorcontroller.SchDoc
size A3
Used 2 times, as channels U_Top_Sheet1/U_Motorcontroller, U_Top_Sheet2/U_Motorcontroller. Parts and nets are listed once, with the designators drawn on the sheet.
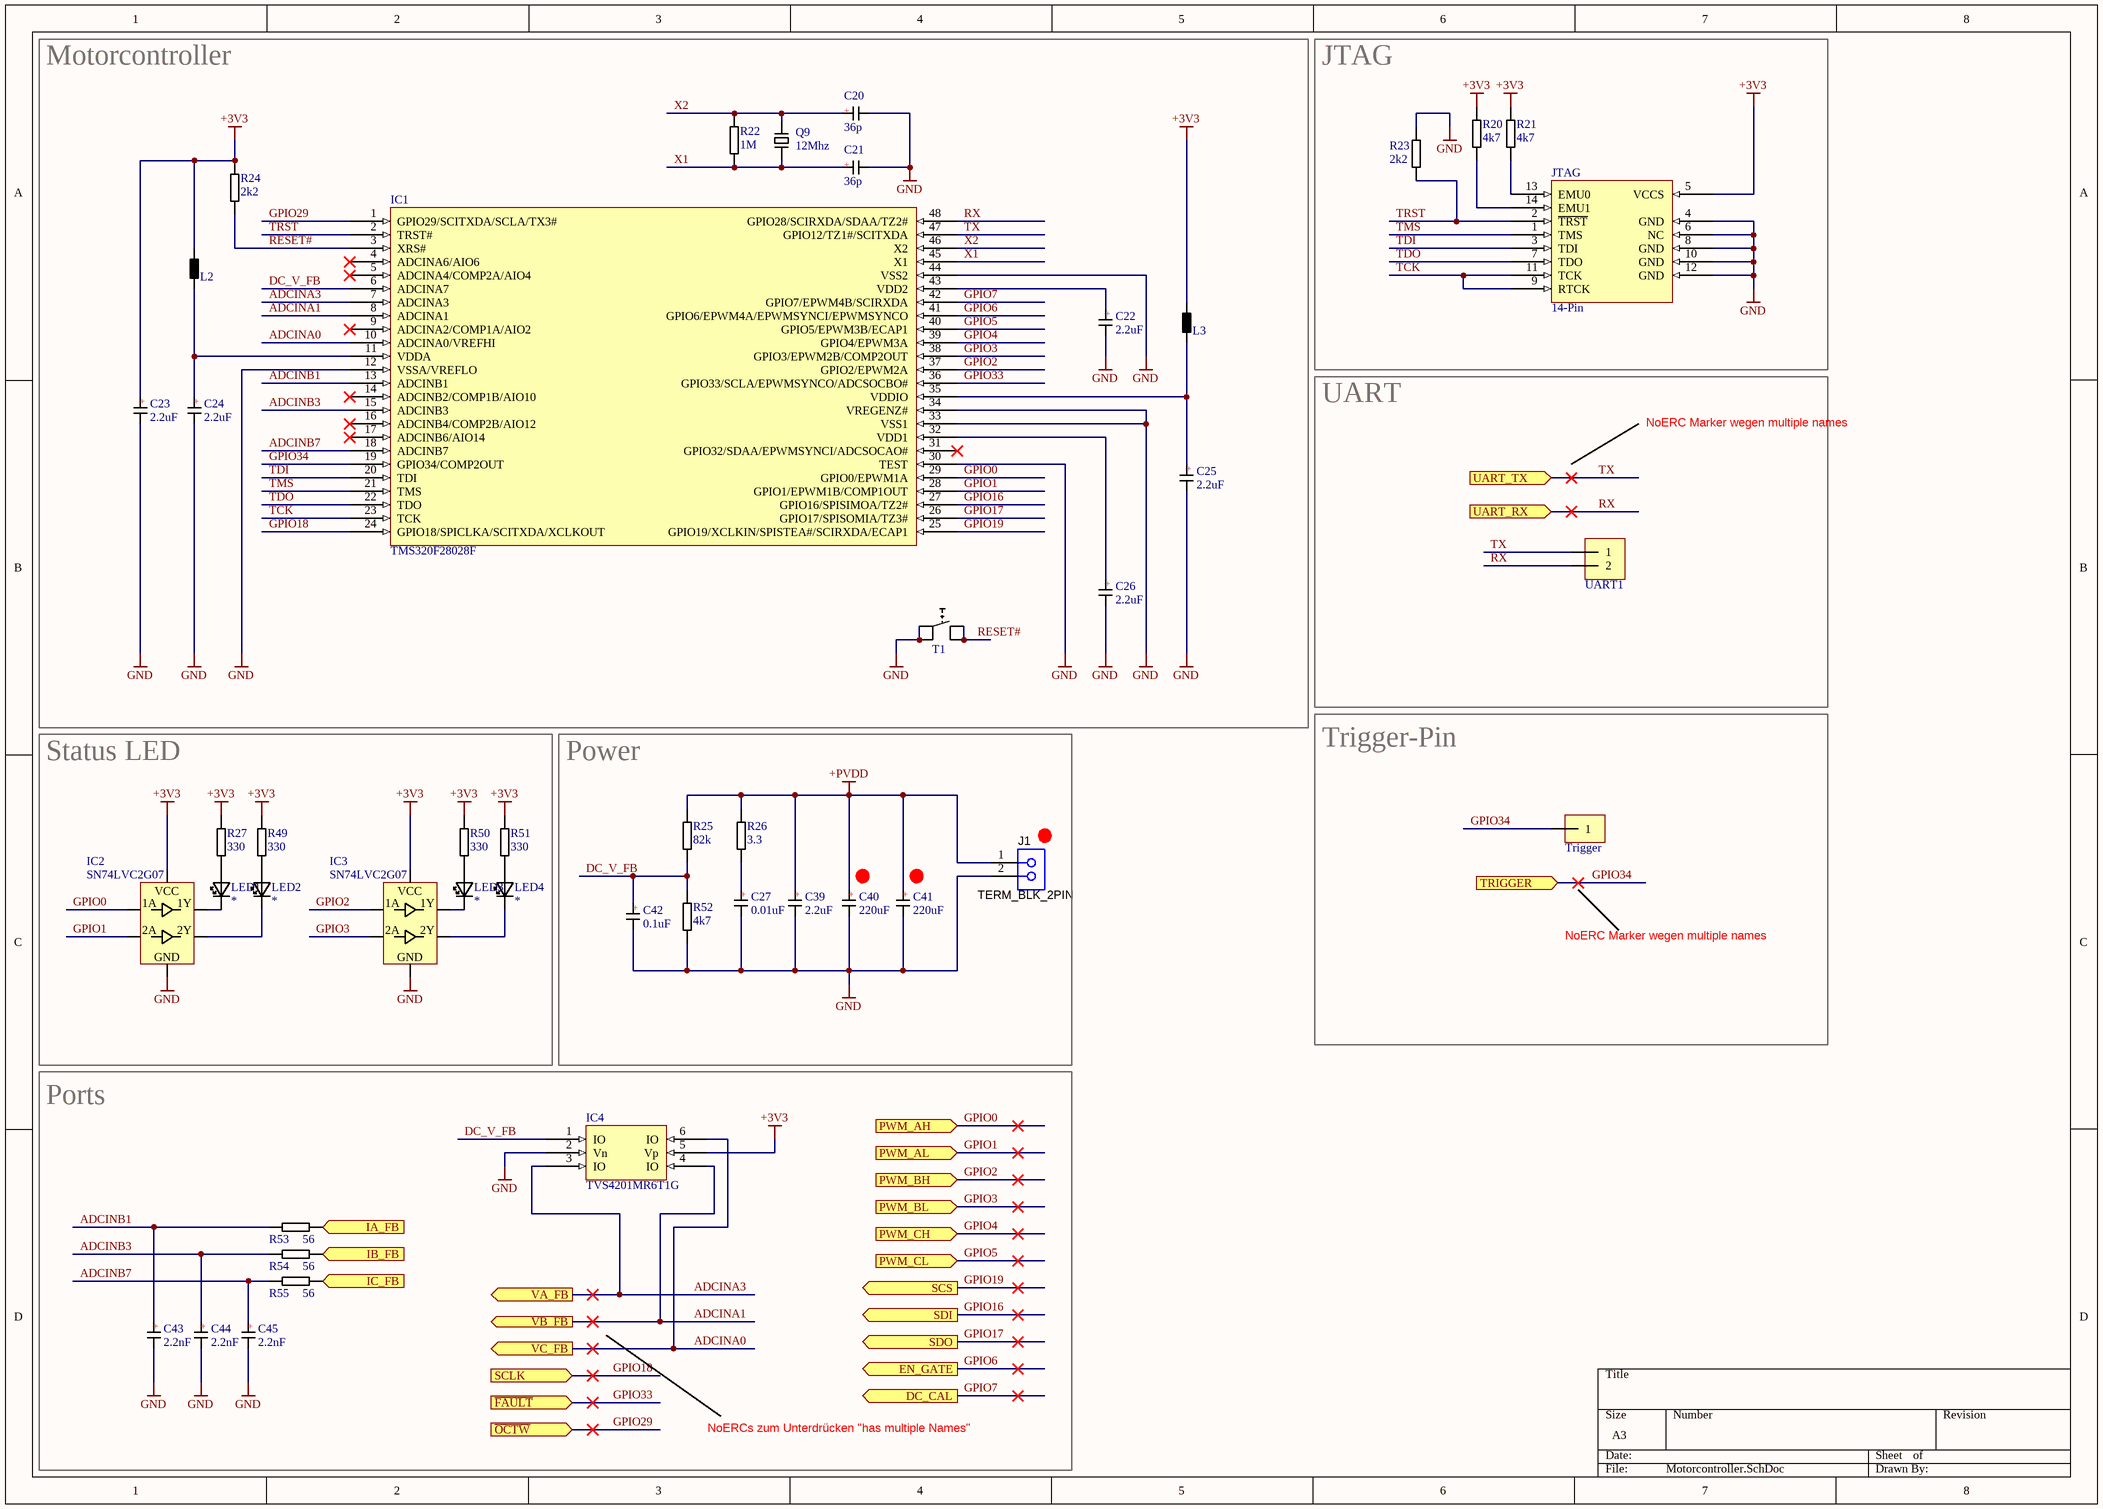
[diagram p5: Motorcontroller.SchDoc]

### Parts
C20  value 36p  [0603]  (hidden comment: Capacitor)
C21  value 36p  [0603]  (hidden comment: Capacitor)
C22  value 2.2uF  [0603]  (hidden comment: Capacitor)
C23  value 2.2uF  [0603]  (hidden comment: Capacitor)
C24  value 2.2uF  [0603]  (hidden comment: Capacitor)
C25  value 2.2uF  [0603]  (hidden comment: Capacitor)
C26  value 2.2uF  [0603]  (hidden comment: Capacitor)
C27  value 0.01uF  [0603]  (hidden comment: Capacitor)
C39  value 2.2uF  [0603]  (hidden comment: Capacitor)
C40  value 220uF  [0603]  (hidden comment: Capacitor)
C41  value 220uF  [0603]  (hidden comment: Capacitor)
C42  value 0.1uF  [0603]  (hidden comment: Capacitor)
C43  value 2.2nF  [0603]  (hidden comment: Capacitor)
C44  value 2.2nF  [0603]  (hidden comment: Capacitor)
C45  value 2.2nF  [0603]  (hidden comment: Capacitor)
IC1  TMS320F28028F  [LQFP48]
IC2  SN74LVC2G07  [SOT23-6]
IC3  SN74LVC2G07  [SOT23-6]
IC4  TVS4201MR6T1G  [TSOP-6]
J1  TERM_BLK_2PIN  [CONN_ED120-2DS]
JTAG  14-Pin  [DC3-14P]
L2  Induktion / Spule / Inductor  [0603]  (value not drawn)
L3  Induktion / Spule / Inductor  [0603]  (value not drawn)
LED1  LED  [1206_Green]  (value not drawn)
LED2  LED  [1206_Green]  (value not drawn)
LED3  LED  [1206_Green]  (value not drawn)
LED4  LED  [1206_Green]  (value not drawn)
Q9  value 12Mhz  [3225]  (hidden comment: Crystal_SMD)
R20  value 4k7  [0603]  (hidden comment: Resistor)
R21  value 4k7  [0603]  (hidden comment: Resistor)
R22  value 1M  [0603]  (hidden comment: Resistor)
R23  value 2k2  [0603]  (hidden comment: Resistor)
R24  value 2k2  [0603]  (hidden comment: Resistor)
R25  value 82k  [0603]  (hidden comment: Resistor)
R26  value 3.3  [0603]  (hidden comment: Resistor)
R27  value 330  [0603]  (hidden comment: Resistor)
R49  value 330  [0603]  (hidden comment: Resistor)
R50  value 330  [0603]  (hidden comment: Resistor)
R51  value 330  [0603]  (hidden comment: Resistor)
R52  value 4k7  [0603]  (hidden comment: Resistor)
R53  value 56  [0603]  (hidden comment: Resistor)
R54  value 56  [0603]  (hidden comment: Resistor)
R55  value 56  [0603]  (hidden comment: Resistor)
T1  Switch  [SMD_4x4]  (value not drawn)
Trigger  Pinhead 1x1  [1x1]  (value not drawn)
UART1  Pinhead 1x2  [1x2]  (value not drawn)

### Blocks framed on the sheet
Motorcontroller: C20-C26 IC1 L2 L3 Q9 R22 R24 T1
JTAG: JTAG R20 R21 R23
UART: UART1
Trigger-Pin: Trigger
Status LED: IC2 IC3 LED1-LED4 R27 R49-R51
Power: C27 C39-C42 J1 R25 R26 R52
Ports: C43-C45 IC4 R53-R55

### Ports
DC_CAL, EN_GATE, IA_FB, IB_FB, IC_FB, PWM_AH, PWM_AL, PWM_BH, PWM_BL, PWM_CH, PWM_CL, SCLK, SCS, SDI, SDO, TRIGGER, UART_RX, UART_TX, VA_FB, VB_FB, VC_FB, ~{FAULT}, ~{OCTW}

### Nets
+3V3: C23.1 IC2.5(VCC) IC3.5(VCC) IC4.5(Vp) JTAG.5(VCCS) L2.2 L3.2 R20.2 R21.2 R24.2 R27.2 R49.2 R50.2 R51.2
+PVDD: C39.1 C40.1 C41.1 J1.1 R25.2 R26.2
GND: C20.2 C21.2 C22.2 C23.2 C24.2 C25.2 C26.2 C27.2 C39.2 C40.2 C41.2 C42.2 C43.2 C44.2 C45.2 IC1.12(VSSA/VREFLO) IC1.30(TEST) IC1.33(VSS1) IC1.34(VREGENZ#) IC1.44(VSS2) IC2.2(GND) IC3.2(GND) IC4.2(Vn) J1.2 JTAG.4(GND) JTAG.6(NC) JTAG.8(GND) JTAG.10(GND) JTAG.12(GND) Q9.2 Q9.4 R23.2 R52.1 T1.1 T1.2
ADCINA0: IC1.10(ADCINA0/VREFHI) IC4.6(IO) ; port VC_FB
ADCINA1: IC1.8(ADCINA1) IC4.4(IO) ; port VB_FB
ADCINA3: IC1.7(ADCINA3) IC4.3(IO) ; port VA_FB
ADCINB1: C43.1 IC1.13(ADCINB1) R53.2
ADCINB3: C44.1 IC1.15(ADCINB3) R54.2
ADCINB7: C45.1 IC1.18(ADCINB7) R55.2
DC_V_FB: C42.1 IC1.6(ADCINA7) IC4.1(IO) R25.1 R52.2
GPIO0: IC1.29(GPIO0/EPWM1A) IC2.1(1A) ; port PWM_AH
GPIO1: IC1.28(GPIO1/EPWM1B/COMP1OUT) IC2.3(2A) ; port PWM_AL
GPIO2: IC1.37(GPIO2/EPWM2A) IC3.1(1A) ; port PWM_BH
GPIO3: IC1.38(GPIO3/EPWM2B/COMP2OUT) IC3.3(2A) ; port PWM_BL
GPIO4: IC1.39(GPIO4/EPWM3A) ; port PWM_CH
GPIO5: IC1.40(GPIO5/EPWM3B/ECAP1) ; port PWM_CL
GPIO6: IC1.41(GPIO6/EPWM4A/EPWMSYNCI/EPWMSYNCO) ; port EN_GATE
GPIO7: IC1.42(GPIO7/EPWM4B/SCIRXDA) ; port DC_CAL
GPIO16: IC1.27(GPIO16/SPISIMOA/TZ2#) ; port SDI
GPIO17: IC1.26(GPIO17/SPISOMIA/TZ3#) ; port SDO
GPIO18: IC1.24(GPIO18/SPICLKA/SCITXDA/XCLKOUT) ; port SCLK
GPIO19: IC1.25(GPIO19/XCLKIN/SPISTEA#/SCIRXDA/ECAP1) ; port SCS
GPIO29: IC1.1(GPIO29/SCITXDA/SCLA/TX3#) ; port ~{OCTW}
GPIO33: IC1.36(GPIO33/SCLA/EPWMSYNCO/ADCSOCBO#) ; port ~{FAULT}
GPIO34: IC1.19(GPIO34/COMP2OUT) Trigger.1 ; port TRIGGER
IA_FB: R53.1 ; port IA_FB
IB_FB: R54.1 ; port IB_FB
IC_FB: R55.1 ; port IC_FB
RESET#: IC1.3(XRS#) R24.1 T1.3 T1.4
RX: IC1.48(GPIO28/SCIRXDA/SDAA/TZ2#) UART1.2 ; port UART_RX
TCK: IC1.23(TCK) JTAG.9(RTCK) JTAG.11(TCK)
TDI: IC1.20(TDI) JTAG.3(TDI)
TDO: IC1.22(TDO) JTAG.7(TDO)
TMS: IC1.21(TMS) JTAG.1(TMS)
TRST: IC1.2(TRST#) JTAG.2(~{TRST}) R23.1
TX: IC1.47(GPIO12/TZ1#/SCITXDA) UART1.1 ; port UART_TX
X1: C21.1 IC1.45(X1) Q9.3 R22.1
X2: C20.1 IC1.46(X2) Q9.1 R22.2
NetC22_1: C22.1 IC1.43(VDD2)
NetC24_1: C24.1 IC1.11(VDDA) L2.1
NetC25_1: C25.1 IC1.35(VDDIO) L3.1
NetC26_1: C26.1 IC1.32(VDD1)
NetC27_1: C27.1 R26.1
NetIC2_4: IC2.4(2Y) LED2.2
NetIC2_6: IC2.6(1Y) LED1.2
NetIC3_4: IC3.4(2Y) LED4.2
NetIC3_6: IC3.6(1Y) LED3.2
NetJTAG_13: JTAG.13(EMU0) R21.1
NetJTAG_14: JTAG.14(EMU1) R20.1
NetLED1_1: LED1.1 R27.1
NetLED2_1: LED2.1 R49.1
NetLED3_1: LED3.1 R50.1
NetLED4_1: LED4.1 R51.1

Not connected (* = marked no-connect by the designer): IC1 4(ADCINA6/AIO6)* 5(ADCINA4/COMP2A/AIO4)* 9(ADCINA2/COMP1A/AIO2)* 14(ADCINB2/COMP1B/AIO10)* 16(ADCINB4/COMP2B/AIO12)* 17(ADCINB6/AIO14)* 31(GPIO32/SDAA/EPWMSYNCI/ADCSOCAO#)*

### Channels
U_Top_Sheet1/U_Motorcontroller: designators end in _U_Top_Sheet1_U_Motorcontroller; ports DC_CAL=DC_CAL EN_GATE=EN_GATE IA_FB=IA_FB IB_FB=IB_FB IC_FB=IC_FB_U_Top_Sheet1 PWM_AH=GPIO0 PWM_AL=GPIO1 PWM_BH=GPIO2 PWM_BL=GPIO3 PWM_CH=GPIO4 PWM_CL=GPIO5 SCLK=GPIO18 SCS=GPIO19 SDI=GPIO16 SDO=GPIO17 TRIGGER=Trigger UART_RX=UART_RX1 UART_TX=UART_TX1 VA_FB=VA_FB_U_Top_Sheet1 VB_FB=VB_FB_U_Top_Sheet1 VC_FB=VC_FB_U_Top_Sheet1 ~{FAULT}=~{FAULT} ~{OCTW}=~{OCTW}
U_Top_Sheet2/U_Motorcontroller: designators end in _U_Top_Sheet2_U_Motorcontroller; ports DC_CAL=DC_CAL EN_GATE=EN_GATE IA_FB=IA_FB IB_FB=IB_FB IC_FB=IC_FB_U_Top_Sheet2 PWM_AH=GPIO0 PWM_AL=GPIO1 PWM_BH=GPIO2 PWM_BL=GPIO3 PWM_CH=GPIO4 PWM_CL=GPIO5 SCLK=GPIO18 SCS=GPIO19 SDI=GPIO16 SDO=GPIO17 TRIGGER=Trigger UART_RX=UART_RX2 UART_TX=UART_TX2 VA_FB=VA_FB_U_Top_Sheet2 VB_FB=VB_FB_U_Top_Sheet2 VC_FB=VC_FB_U_Top_Sheet2 ~{FAULT}=~{FAULT} ~{OCTW}=~{OCTW}

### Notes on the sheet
- NoERC Marker wegen multiple names
- NoERCs zum Unterdrücken "has multiple Names"

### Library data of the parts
C20-C27 C39-C45 = Capacitor: Capacitor, Generic
IC1 = TMS320F28027F: TMS320F2802x Piccolo™ Microcontrollers
IC2 IC3 = SN74LVC2G07: SN74LVC2G07 Dual Buffer and Driver With Open-Drain Outputs
IC4 = TVS4201MR6: TVS4201MR6T1G - Transient Voltage  Suppressors  Low Clamping Voltage Surge Protection  Diode Array  The TVS4201MR6 transient voltage suppressor is designed to  protect high speed data lines from ESD, EFT, and lightning surges.
J1 = ED120/2DS: TERMINAL BLOCK 5.08MM VERT 2POS; PartNumber: OSTTA024163; Manufacturer: On-Shore Technology; U/M: EA; Value: 2 Pin Header
JTAG = JTAG 14-Pin: JTAG 14 Pin Connector
L2 L3 = Induktion / Spule / Inductor: Induktion
LED1-LED4 = LED: LED 0206 China
Q9 = Crystal_SMD: Quarz / Crystal
R20-R27 R49-R55 = Resistor: Resistor, Generic
T1 = Switch: Different switches, Taster

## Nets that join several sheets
+3.3V: U_Top_Sheet1/U_SENSE (C37_U_Top_Sheet1_U_SENSE.2 IC5_U_Top_Sheet1_U_SENSE.8 R46_U_Top_Sheet1_U_SENSE.2), U_Top_Sheet1/U_DRV8301 (10 pins), U_Top_Sheet2/U_SENSE (C37_U_Top_Sheet2_U_SENSE.2 IC5_U_Top_Sheet2_U_SENSE.8 R46_U_Top_Sheet2_U_SENSE.2), U_Top_Sheet2/U_DRV8301 (10 pins)
+3V3: Mastercontroller (42 pins), U_Top_Sheet1/U_Motorcontroller (14 pins), U_Top_Sheet2/U_Motorcontroller (14 pins)
+PVDD: U_Top_Sheet1/U_MOTOR (6 pins), U_Top_Sheet1/U_DRV8301 (7 pins), U_Top_Sheet1/U_Motorcontroller (6 pins), U_Top_Sheet2/U_MOTOR (6 pins), U_Top_Sheet2/U_DRV8301 (7 pins), U_Top_Sheet2/U_Motorcontroller (6 pins)
DVDD: U_Top_Sheet1/U_DRV8301 (C17_U_Top_Sheet1_U_DRV8301.2 U1_U_Top_Sheet1_U_DRV8301.23), U_Top_Sheet2/U_DRV8301 (C17_U_Top_Sheet2_U_DRV8301.2 U1_U_Top_Sheet2_U_DRV8301.23)
GND: Mastercontroller (41 pins), U_Top_Sheet1/U_MOTOR (9 pins), U_Top_Sheet1/U_SENSE (10 pins), U_Top_Sheet1/U_DRV8301 (21 pins), U_Top_Sheet1/U_Motorcontroller (35 pins), U_Top_Sheet2/U_MOTOR (9 pins), U_Top_Sheet2/U_SENSE (10 pins), U_Top_Sheet2/U_DRV8301 (21 pins), U_Top_Sheet2/U_Motorcontroller (35 pins)
~{FAULT}: U_Top_Sheet1/U_DRV8301 (R3_U_Top_Sheet1_U_DRV8301.2 U1_U_Top_Sheet1_U_DRV8301.6), U_Top_Sheet1/U_Motorcontroller (IC1_U_Top_Sheet1_U_Motorcontroller.36)
~{FAULT}: U_Top_Sheet2/U_DRV8301 (R3_U_Top_Sheet2_U_DRV8301.2 U1_U_Top_Sheet2_U_DRV8301.6), U_Top_Sheet2/U_Motorcontroller (IC1_U_Top_Sheet2_U_Motorcontroller.36)
~{OCTW}: U_Top_Sheet1/U_DRV8301 (R2_U_Top_Sheet1_U_DRV8301.2 U1_U_Top_Sheet1_U_DRV8301.5), U_Top_Sheet1/U_Motorcontroller (IC1_U_Top_Sheet1_U_Motorcontroller.1)
~{OCTW}: U_Top_Sheet2/U_DRV8301 (R2_U_Top_Sheet2_U_DRV8301.2 U1_U_Top_Sheet2_U_DRV8301.5), U_Top_Sheet2/U_Motorcontroller (IC1_U_Top_Sheet2_U_Motorcontroller.1)
A_ISENSE_N: U_Top_Sheet1/U_MOTOR (C31_U_Top_Sheet1_U_MOTOR.1 J8_U_Top_Sheet1_U_MOTOR.2), U_Top_Sheet1/U_DRV8301 (U1_U_Top_Sheet1_U_DRV8301.32)
A_ISENSE_N: U_Top_Sheet2/U_MOTOR (C31_U_Top_Sheet2_U_MOTOR.1 J8_U_Top_Sheet2_U_MOTOR.2), U_Top_Sheet2/U_DRV8301 (U1_U_Top_Sheet2_U_DRV8301.32)
A_ISENSE_P: U_Top_Sheet1/U_MOTOR (C31_U_Top_Sheet1_U_MOTOR.2 J5_U_Top_Sheet1_U_MOTOR.2), U_Top_Sheet1/U_DRV8301 (U1_U_Top_Sheet1_U_DRV8301.33)
A_ISENSE_P: U_Top_Sheet2/U_MOTOR (C31_U_Top_Sheet2_U_MOTOR.2 J5_U_Top_Sheet2_U_MOTOR.2), U_Top_Sheet2/U_DRV8301 (U1_U_Top_Sheet2_U_DRV8301.33)
B_ISENSE_N: U_Top_Sheet1/U_MOTOR (C32_U_Top_Sheet1_U_MOTOR.1 J9_U_Top_Sheet1_U_MOTOR.2), U_Top_Sheet1/U_DRV8301 (U1_U_Top_Sheet1_U_DRV8301.30)
B_ISENSE_N: U_Top_Sheet2/U_MOTOR (C32_U_Top_Sheet2_U_MOTOR.1 J9_U_Top_Sheet2_U_MOTOR.2), U_Top_Sheet2/U_DRV8301 (U1_U_Top_Sheet2_U_DRV8301.30)
B_ISENSE_P: U_Top_Sheet1/U_MOTOR (C32_U_Top_Sheet1_U_MOTOR.2 J6_U_Top_Sheet1_U_MOTOR.2), U_Top_Sheet1/U_DRV8301 (U1_U_Top_Sheet1_U_DRV8301.31)
B_ISENSE_P: U_Top_Sheet2/U_MOTOR (C32_U_Top_Sheet2_U_MOTOR.2 J6_U_Top_Sheet2_U_MOTOR.2), U_Top_Sheet2/U_DRV8301 (U1_U_Top_Sheet2_U_DRV8301.31)
C_ISENSE_N: U_Top_Sheet1/U_MOTOR (C33_U_Top_Sheet1_U_MOTOR.1 J10_U_Top_Sheet1_U_MOTOR.2), U_Top_Sheet1/U_SENSE (R45_U_Top_Sheet1_U_SENSE.1)
C_ISENSE_N: U_Top_Sheet2/U_MOTOR (C33_U_Top_Sheet2_U_MOTOR.1 J10_U_Top_Sheet2_U_MOTOR.2), U_Top_Sheet2/U_SENSE (R45_U_Top_Sheet2_U_SENSE.1)
C_ISENSE_P: U_Top_Sheet1/U_MOTOR (C33_U_Top_Sheet1_U_MOTOR.2 J7_U_Top_Sheet1_U_MOTOR.2), U_Top_Sheet1/U_SENSE (R44_U_Top_Sheet1_U_SENSE.1)
C_ISENSE_P: U_Top_Sheet2/U_MOTOR (C33_U_Top_Sheet2_U_MOTOR.2 J7_U_Top_Sheet2_U_MOTOR.2), U_Top_Sheet2/U_SENSE (R44_U_Top_Sheet2_U_SENSE.1)
DC_CAL: U_Top_Sheet1/U_DRV8301 (R9_U_Top_Sheet1_U_DRV8301.1 U1_U_Top_Sheet1_U_DRV8301.12), U_Top_Sheet1/U_Motorcontroller (IC1_U_Top_Sheet1_U_Motorcontroller.42)
DC_CAL: U_Top_Sheet2/U_DRV8301 (R9_U_Top_Sheet2_U_DRV8301.1 U1_U_Top_Sheet2_U_DRV8301.12), U_Top_Sheet2/U_Motorcontroller (IC1_U_Top_Sheet2_U_Motorcontroller.42)
EN_GATE: U_Top_Sheet1/U_DRV8301 (R6_U_Top_Sheet1_U_DRV8301.1 U1_U_Top_Sheet1_U_DRV8301.16), U_Top_Sheet1/U_Motorcontroller (IC1_U_Top_Sheet1_U_Motorcontroller.41)
EN_GATE: U_Top_Sheet2/U_DRV8301 (R6_U_Top_Sheet2_U_DRV8301.1 U1_U_Top_Sheet2_U_DRV8301.16), U_Top_Sheet2/U_Motorcontroller (IC1_U_Top_Sheet2_U_Motorcontroller.41)
GH_A: U_Top_Sheet1/U_MOTOR (R28_U_Top_Sheet1_U_MOTOR.2), U_Top_Sheet1/U_DRV8301 (U1_U_Top_Sheet1_U_DRV8301.47)
GH_A: U_Top_Sheet2/U_MOTOR (R28_U_Top_Sheet2_U_MOTOR.2), U_Top_Sheet2/U_DRV8301 (U1_U_Top_Sheet2_U_DRV8301.47)
GH_B: U_Top_Sheet1/U_MOTOR (R29_U_Top_Sheet1_U_MOTOR.2), U_Top_Sheet1/U_DRV8301 (U1_U_Top_Sheet1_U_DRV8301.42)
GH_B: U_Top_Sheet2/U_MOTOR (R29_U_Top_Sheet2_U_MOTOR.2), U_Top_Sheet2/U_DRV8301 (U1_U_Top_Sheet2_U_DRV8301.42)
GH_C: U_Top_Sheet1/U_MOTOR (R30_U_Top_Sheet1_U_MOTOR.2), U_Top_Sheet1/U_DRV8301 (U1_U_Top_Sheet1_U_DRV8301.37)
GH_C: U_Top_Sheet2/U_MOTOR (R30_U_Top_Sheet2_U_MOTOR.2), U_Top_Sheet2/U_DRV8301 (U1_U_Top_Sheet2_U_DRV8301.37)
GL_A: U_Top_Sheet1/U_MOTOR (R31_U_Top_Sheet1_U_MOTOR.2), U_Top_Sheet1/U_DRV8301 (U1_U_Top_Sheet1_U_DRV8301.45)
GL_A: U_Top_Sheet2/U_MOTOR (R31_U_Top_Sheet2_U_MOTOR.2), U_Top_Sheet2/U_DRV8301 (U1_U_Top_Sheet2_U_DRV8301.45)
GL_B: U_Top_Sheet1/U_MOTOR (R32_U_Top_Sheet1_U_MOTOR.2), U_Top_Sheet1/U_DRV8301 (U1_U_Top_Sheet1_U_DRV8301.40)
GL_B: U_Top_Sheet2/U_MOTOR (R32_U_Top_Sheet2_U_MOTOR.2), U_Top_Sheet2/U_DRV8301 (U1_U_Top_Sheet2_U_DRV8301.40)
GL_C: U_Top_Sheet1/U_MOTOR (R33_U_Top_Sheet1_U_MOTOR.2), U_Top_Sheet1/U_DRV8301 (U1_U_Top_Sheet1_U_DRV8301.35)
GL_C: U_Top_Sheet2/U_MOTOR (R33_U_Top_Sheet2_U_MOTOR.2), U_Top_Sheet2/U_DRV8301 (U1_U_Top_Sheet2_U_DRV8301.35)
GPIO0: U_Top_Sheet1/U_DRV8301 (U1_U_Top_Sheet1_U_DRV8301.17), U_Top_Sheet1/U_Motorcontroller (IC1_U_Top_Sheet1_U_Motorcontroller.29 IC2_U_Top_Sheet1_U_Motorcontroller.1)
GPIO0: U_Top_Sheet2/U_DRV8301 (U1_U_Top_Sheet2_U_DRV8301.17), U_Top_Sheet2/U_Motorcontroller (IC1_U_Top_Sheet2_U_Motorcontroller.29 IC2_U_Top_Sheet2_U_Motorcontroller.1)
GPIO1: U_Top_Sheet1/U_DRV8301 (U1_U_Top_Sheet1_U_DRV8301.18), U_Top_Sheet1/U_Motorcontroller (IC1_U_Top_Sheet1_U_Motorcontroller.28 IC2_U_Top_Sheet1_U_Motorcontroller.3)
GPIO1: U_Top_Sheet2/U_DRV8301 (U1_U_Top_Sheet2_U_DRV8301.18), U_Top_Sheet2/U_Motorcontroller (IC1_U_Top_Sheet2_U_Motorcontroller.28 IC2_U_Top_Sheet2_U_Motorcontroller.3)
GPIO2: U_Top_Sheet1/U_DRV8301 (U1_U_Top_Sheet1_U_DRV8301.19), U_Top_Sheet1/U_Motorcontroller (IC1_U_Top_Sheet1_U_Motorcontroller.37 IC3_U_Top_Sheet1_U_Motorcontroller.1)
GPIO2: U_Top_Sheet2/U_DRV8301 (U1_U_Top_Sheet2_U_DRV8301.19), U_Top_Sheet2/U_Motorcontroller (IC1_U_Top_Sheet2_U_Motorcontroller.37 IC3_U_Top_Sheet2_U_Motorcontroller.1)
GPIO3: U_Top_Sheet1/U_DRV8301 (U1_U_Top_Sheet1_U_DRV8301.20), U_Top_Sheet1/U_Motorcontroller (IC1_U_Top_Sheet1_U_Motorcontroller.38 IC3_U_Top_Sheet1_U_Motorcontroller.3)
GPIO3: U_Top_Sheet2/U_DRV8301 (U1_U_Top_Sheet2_U_DRV8301.20), U_Top_Sheet2/U_Motorcontroller (IC1_U_Top_Sheet2_U_Motorcontroller.38 IC3_U_Top_Sheet2_U_Motorcontroller.3)
GPIO4: U_Top_Sheet1/U_DRV8301 (U1_U_Top_Sheet1_U_DRV8301.21), U_Top_Sheet1/U_Motorcontroller (IC1_U_Top_Sheet1_U_Motorcontroller.39)
GPIO4: U_Top_Sheet2/U_DRV8301 (U1_U_Top_Sheet2_U_DRV8301.21), U_Top_Sheet2/U_Motorcontroller (IC1_U_Top_Sheet2_U_Motorcontroller.39)
GPIO5: U_Top_Sheet1/U_DRV8301 (U1_U_Top_Sheet1_U_DRV8301.22), U_Top_Sheet1/U_Motorcontroller (IC1_U_Top_Sheet1_U_Motorcontroller.40)
GPIO5: U_Top_Sheet2/U_DRV8301 (U1_U_Top_Sheet2_U_DRV8301.22), U_Top_Sheet2/U_Motorcontroller (IC1_U_Top_Sheet2_U_Motorcontroller.40)
GPIO16: U_Top_Sheet1/U_DRV8301 (U1_U_Top_Sheet1_U_DRV8301.9), U_Top_Sheet1/U_Motorcontroller (IC1_U_Top_Sheet1_U_Motorcontroller.27)
GPIO16: U_Top_Sheet2/U_DRV8301 (U1_U_Top_Sheet2_U_DRV8301.9), U_Top_Sheet2/U_Motorcontroller (IC1_U_Top_Sheet2_U_Motorcontroller.27)
GPIO17: U_Top_Sheet1/U_DRV8301 (U1_U_Top_Sheet1_U_DRV8301.10), U_Top_Sheet1/U_Motorcontroller (IC1_U_Top_Sheet1_U_Motorcontroller.26)
GPIO17: U_Top_Sheet2/U_DRV8301 (U1_U_Top_Sheet2_U_DRV8301.10), U_Top_Sheet2/U_Motorcontroller (IC1_U_Top_Sheet2_U_Motorcontroller.26)
GPIO18: U_Top_Sheet1/U_DRV8301 (U1_U_Top_Sheet1_U_DRV8301.11), U_Top_Sheet1/U_Motorcontroller (IC1_U_Top_Sheet1_U_Motorcontroller.24)
GPIO18: U_Top_Sheet2/U_DRV8301 (U1_U_Top_Sheet2_U_DRV8301.11), U_Top_Sheet2/U_Motorcontroller (IC1_U_Top_Sheet2_U_Motorcontroller.24)
GPIO19: U_Top_Sheet1/U_DRV8301 (U1_U_Top_Sheet1_U_DRV8301.8), U_Top_Sheet1/U_Motorcontroller (IC1_U_Top_Sheet1_U_Motorcontroller.25)
GPIO19: U_Top_Sheet2/U_DRV8301 (U1_U_Top_Sheet2_U_DRV8301.8), U_Top_Sheet2/U_Motorcontroller (IC1_U_Top_Sheet2_U_Motorcontroller.25)
IA_FB: U_Top_Sheet1/U_DRV8301 (U1_U_Top_Sheet1_U_DRV8301.25), U_Top_Sheet1/U_Motorcontroller (R53_U_Top_Sheet1_U_Motorcontroller.1)
IA_FB: U_Top_Sheet2/U_DRV8301 (U1_U_Top_Sheet2_U_DRV8301.25), U_Top_Sheet2/U_Motorcontroller (R53_U_Top_Sheet2_U_Motorcontroller.1)
IB_FB: U_Top_Sheet1/U_DRV8301 (U1_U_Top_Sheet1_U_DRV8301.26), U_Top_Sheet1/U_Motorcontroller (R54_U_Top_Sheet1_U_Motorcontroller.1)
IB_FB: U_Top_Sheet2/U_DRV8301 (U1_U_Top_Sheet2_U_DRV8301.26), U_Top_Sheet2/U_Motorcontroller (R54_U_Top_Sheet2_U_Motorcontroller.1)
IC_FB_U_Top_Sheet1: U_Top_Sheet1/U_SENSE (IC5_U_Top_Sheet1_U_SENSE.1 R43_U_Top_Sheet1_U_SENSE.2), U_Top_Sheet1/U_Motorcontroller (R55_U_Top_Sheet1_U_Motorcontroller.1)
IC_FB_U_Top_Sheet2: U_Top_Sheet2/U_SENSE (IC5_U_Top_Sheet2_U_SENSE.1 R43_U_Top_Sheet2_U_SENSE.2), U_Top_Sheet2/U_Motorcontroller (R55_U_Top_Sheet2_U_Motorcontroller.1)
SH_A: U_Top_Sheet1/U_MOTOR (Q3_U_Top_Sheet1_U_MOTOR.1 Q6_U_Top_Sheet1_U_MOTOR.3), U_Top_Sheet1/U_SENSE (R37_U_Top_Sheet1_U_SENSE.2), U_Top_Sheet1/U_DRV8301 (C5_U_Top_Sheet1_U_DRV8301.1 U1_U_Top_Sheet1_U_DRV8301.46)
SH_A: U_Top_Sheet2/U_MOTOR (Q3_U_Top_Sheet2_U_MOTOR.1 Q6_U_Top_Sheet2_U_MOTOR.3), U_Top_Sheet2/U_SENSE (R37_U_Top_Sheet2_U_SENSE.2), U_Top_Sheet2/U_DRV8301 (C5_U_Top_Sheet2_U_DRV8301.1 U1_U_Top_Sheet2_U_DRV8301.46)
SH_B: U_Top_Sheet1/U_MOTOR (Q4_U_Top_Sheet1_U_MOTOR.1 Q7_U_Top_Sheet1_U_MOTOR.3), U_Top_Sheet1/U_SENSE (R39_U_Top_Sheet1_U_SENSE.2), U_Top_Sheet1/U_DRV8301 (C6_U_Top_Sheet1_U_DRV8301.1 U1_U_Top_Sheet1_U_DRV8301.41)
SH_B: U_Top_Sheet2/U_MOTOR (Q4_U_Top_Sheet2_U_MOTOR.1 Q7_U_Top_Sheet2_U_MOTOR.3), U_Top_Sheet2/U_SENSE (R39_U_Top_Sheet2_U_SENSE.2), U_Top_Sheet2/U_DRV8301 (C6_U_Top_Sheet2_U_DRV8301.1 U1_U_Top_Sheet2_U_DRV8301.41)
SH_C: U_Top_Sheet1/U_MOTOR (Q5_U_Top_Sheet1_U_MOTOR.1 Q8_U_Top_Sheet1_U_MOTOR.3), U_Top_Sheet1/U_SENSE (R41_U_Top_Sheet1_U_SENSE.2), U_Top_Sheet1/U_DRV8301 (C7_U_Top_Sheet1_U_DRV8301.1 U1_U_Top_Sheet1_U_DRV8301.36)
SH_C: U_Top_Sheet2/U_MOTOR (Q5_U_Top_Sheet2_U_MOTOR.1 Q8_U_Top_Sheet2_U_MOTOR.3), U_Top_Sheet2/U_SENSE (R41_U_Top_Sheet2_U_SENSE.2), U_Top_Sheet2/U_DRV8301 (C7_U_Top_Sheet2_U_DRV8301.1 U1_U_Top_Sheet2_U_DRV8301.36)
SL_A: U_Top_Sheet1/U_MOTOR (J5_U_Top_Sheet1_U_MOTOR.1 Q6_U_Top_Sheet1_U_MOTOR.1 R34_U_Top_Sheet1_U_MOTOR.2), U_Top_Sheet1/U_DRV8301 (U1_U_Top_Sheet1_U_DRV8301.44)
SL_A: U_Top_Sheet2/U_MOTOR (J5_U_Top_Sheet2_U_MOTOR.1 Q6_U_Top_Sheet2_U_MOTOR.1 R34_U_Top_Sheet2_U_MOTOR.2), U_Top_Sheet2/U_DRV8301 (U1_U_Top_Sheet2_U_DRV8301.44)
SL_B: U_Top_Sheet1/U_MOTOR (J6_U_Top_Sheet1_U_MOTOR.1 Q7_U_Top_Sheet1_U_MOTOR.1 R35_U_Top_Sheet1_U_MOTOR.2), U_Top_Sheet1/U_DRV8301 (U1_U_Top_Sheet1_U_DRV8301.39)
SL_B: U_Top_Sheet2/U_MOTOR (J6_U_Top_Sheet2_U_MOTOR.1 Q7_U_Top_Sheet2_U_MOTOR.1 R35_U_Top_Sheet2_U_MOTOR.2), U_Top_Sheet2/U_DRV8301 (U1_U_Top_Sheet2_U_DRV8301.39)
SL_C: U_Top_Sheet1/U_MOTOR (J7_U_Top_Sheet1_U_MOTOR.1 Q8_U_Top_Sheet1_U_MOTOR.1 R36_U_Top_Sheet1_U_MOTOR.2), U_Top_Sheet1/U_DRV8301 (U1_U_Top_Sheet1_U_DRV8301.34)
SL_C: U_Top_Sheet2/U_MOTOR (J7_U_Top_Sheet2_U_MOTOR.1 Q8_U_Top_Sheet2_U_MOTOR.1 R36_U_Top_Sheet2_U_MOTOR.2), U_Top_Sheet2/U_DRV8301 (U1_U_Top_Sheet2_U_DRV8301.34)
Trigger: Mastercontroller (IC1.43), U_Top_Sheet1/U_Motorcontroller (IC1_U_Top_Sheet1_U_Motorcontroller.19 Trigger_U_Top_Sheet1_U_Motorcontroller.1), U_Top_Sheet2/U_Motorcontroller (IC1_U_Top_Sheet2_U_Motorcontroller.19 Trigger_U_Top_Sheet2_U_Motorcontroller.1)
UART_RX1: Mastercontroller (IC1.31), U_Top_Sheet1/U_Motorcontroller (IC1_U_Top_Sheet1_U_Motorcontroller.48 UART1_U_Top_Sheet1_U_Motorcontroller.2)
UART_RX2: Mastercontroller (IC1.13), U_Top_Sheet2/U_Motorcontroller (IC1_U_Top_Sheet2_U_Motorcontroller.48 UART1_U_Top_Sheet2_U_Motorcontroller.2)
UART_TX1: Mastercontroller (IC1.30), U_Top_Sheet1/U_Motorcontroller (IC1_U_Top_Sheet1_U_Motorcontroller.47 UART1_U_Top_Sheet1_U_Motorcontroller.1)
UART_TX2: Mastercontroller (IC1.12), U_Top_Sheet2/U_Motorcontroller (IC1_U_Top_Sheet2_U_Motorcontroller.47 UART1_U_Top_Sheet2_U_Motorcontroller.1)
VA_FB_U_Top_Sheet1: U_Top_Sheet1/U_SENSE (C34_U_Top_Sheet1_U_SENSE.2 R37_U_Top_Sheet1_U_SENSE.1 R38_U_Top_Sheet1_U_SENSE.2), U_Top_Sheet1/U_Motorcontroller (IC1_U_Top_Sheet1_U_Motorcontroller.7 IC4_U_Top_Sheet1_U_Motorcontroller.3)
VA_FB_U_Top_Sheet2: U_Top_Sheet2/U_SENSE (C34_U_Top_Sheet2_U_SENSE.2 R37_U_Top_Sheet2_U_SENSE.1 R38_U_Top_Sheet2_U_SENSE.2), U_Top_Sheet2/U_Motorcontroller (IC1_U_Top_Sheet2_U_Motorcontroller.7 IC4_U_Top_Sheet2_U_Motorcontroller.3)
VB_FB_U_Top_Sheet1: U_Top_Sheet1/U_SENSE (C35_U_Top_Sheet1_U_SENSE.2 R39_U_Top_Sheet1_U_SENSE.1 R40_U_Top_Sheet1_U_SENSE.2), U_Top_Sheet1/U_Motorcontroller (IC1_U_Top_Sheet1_U_Motorcontroller.8 IC4_U_Top_Sheet1_U_Motorcontroller.4)
VB_FB_U_Top_Sheet2: U_Top_Sheet2/U_SENSE (C35_U_Top_Sheet2_U_SENSE.2 R39_U_Top_Sheet2_U_SENSE.1 R40_U_Top_Sheet2_U_SENSE.2), U_Top_Sheet2/U_Motorcontroller (IC1_U_Top_Sheet2_U_Motorcontroller.8 IC4_U_Top_Sheet2_U_Motorcontroller.4)
VC_FB_U_Top_Sheet1: U_Top_Sheet1/U_SENSE (C36_U_Top_Sheet1_U_SENSE.2 R41_U_Top_Sheet1_U_SENSE.1 R42_U_Top_Sheet1_U_SENSE.2), U_Top_Sheet1/U_Motorcontroller (IC1_U_Top_Sheet1_U_Motorcontroller.10 IC4_U_Top_Sheet1_U_Motorcontroller.6)
VC_FB_U_Top_Sheet2: U_Top_Sheet2/U_SENSE (C36_U_Top_Sheet2_U_SENSE.2 R41_U_Top_Sheet2_U_SENSE.1 R42_U_Top_Sheet2_U_SENSE.2), U_Top_Sheet2/U_Motorcontroller (IC1_U_Top_Sheet2_U_Motorcontroller.10 IC4_U_Top_Sheet2_U_Motorcontroller.6)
